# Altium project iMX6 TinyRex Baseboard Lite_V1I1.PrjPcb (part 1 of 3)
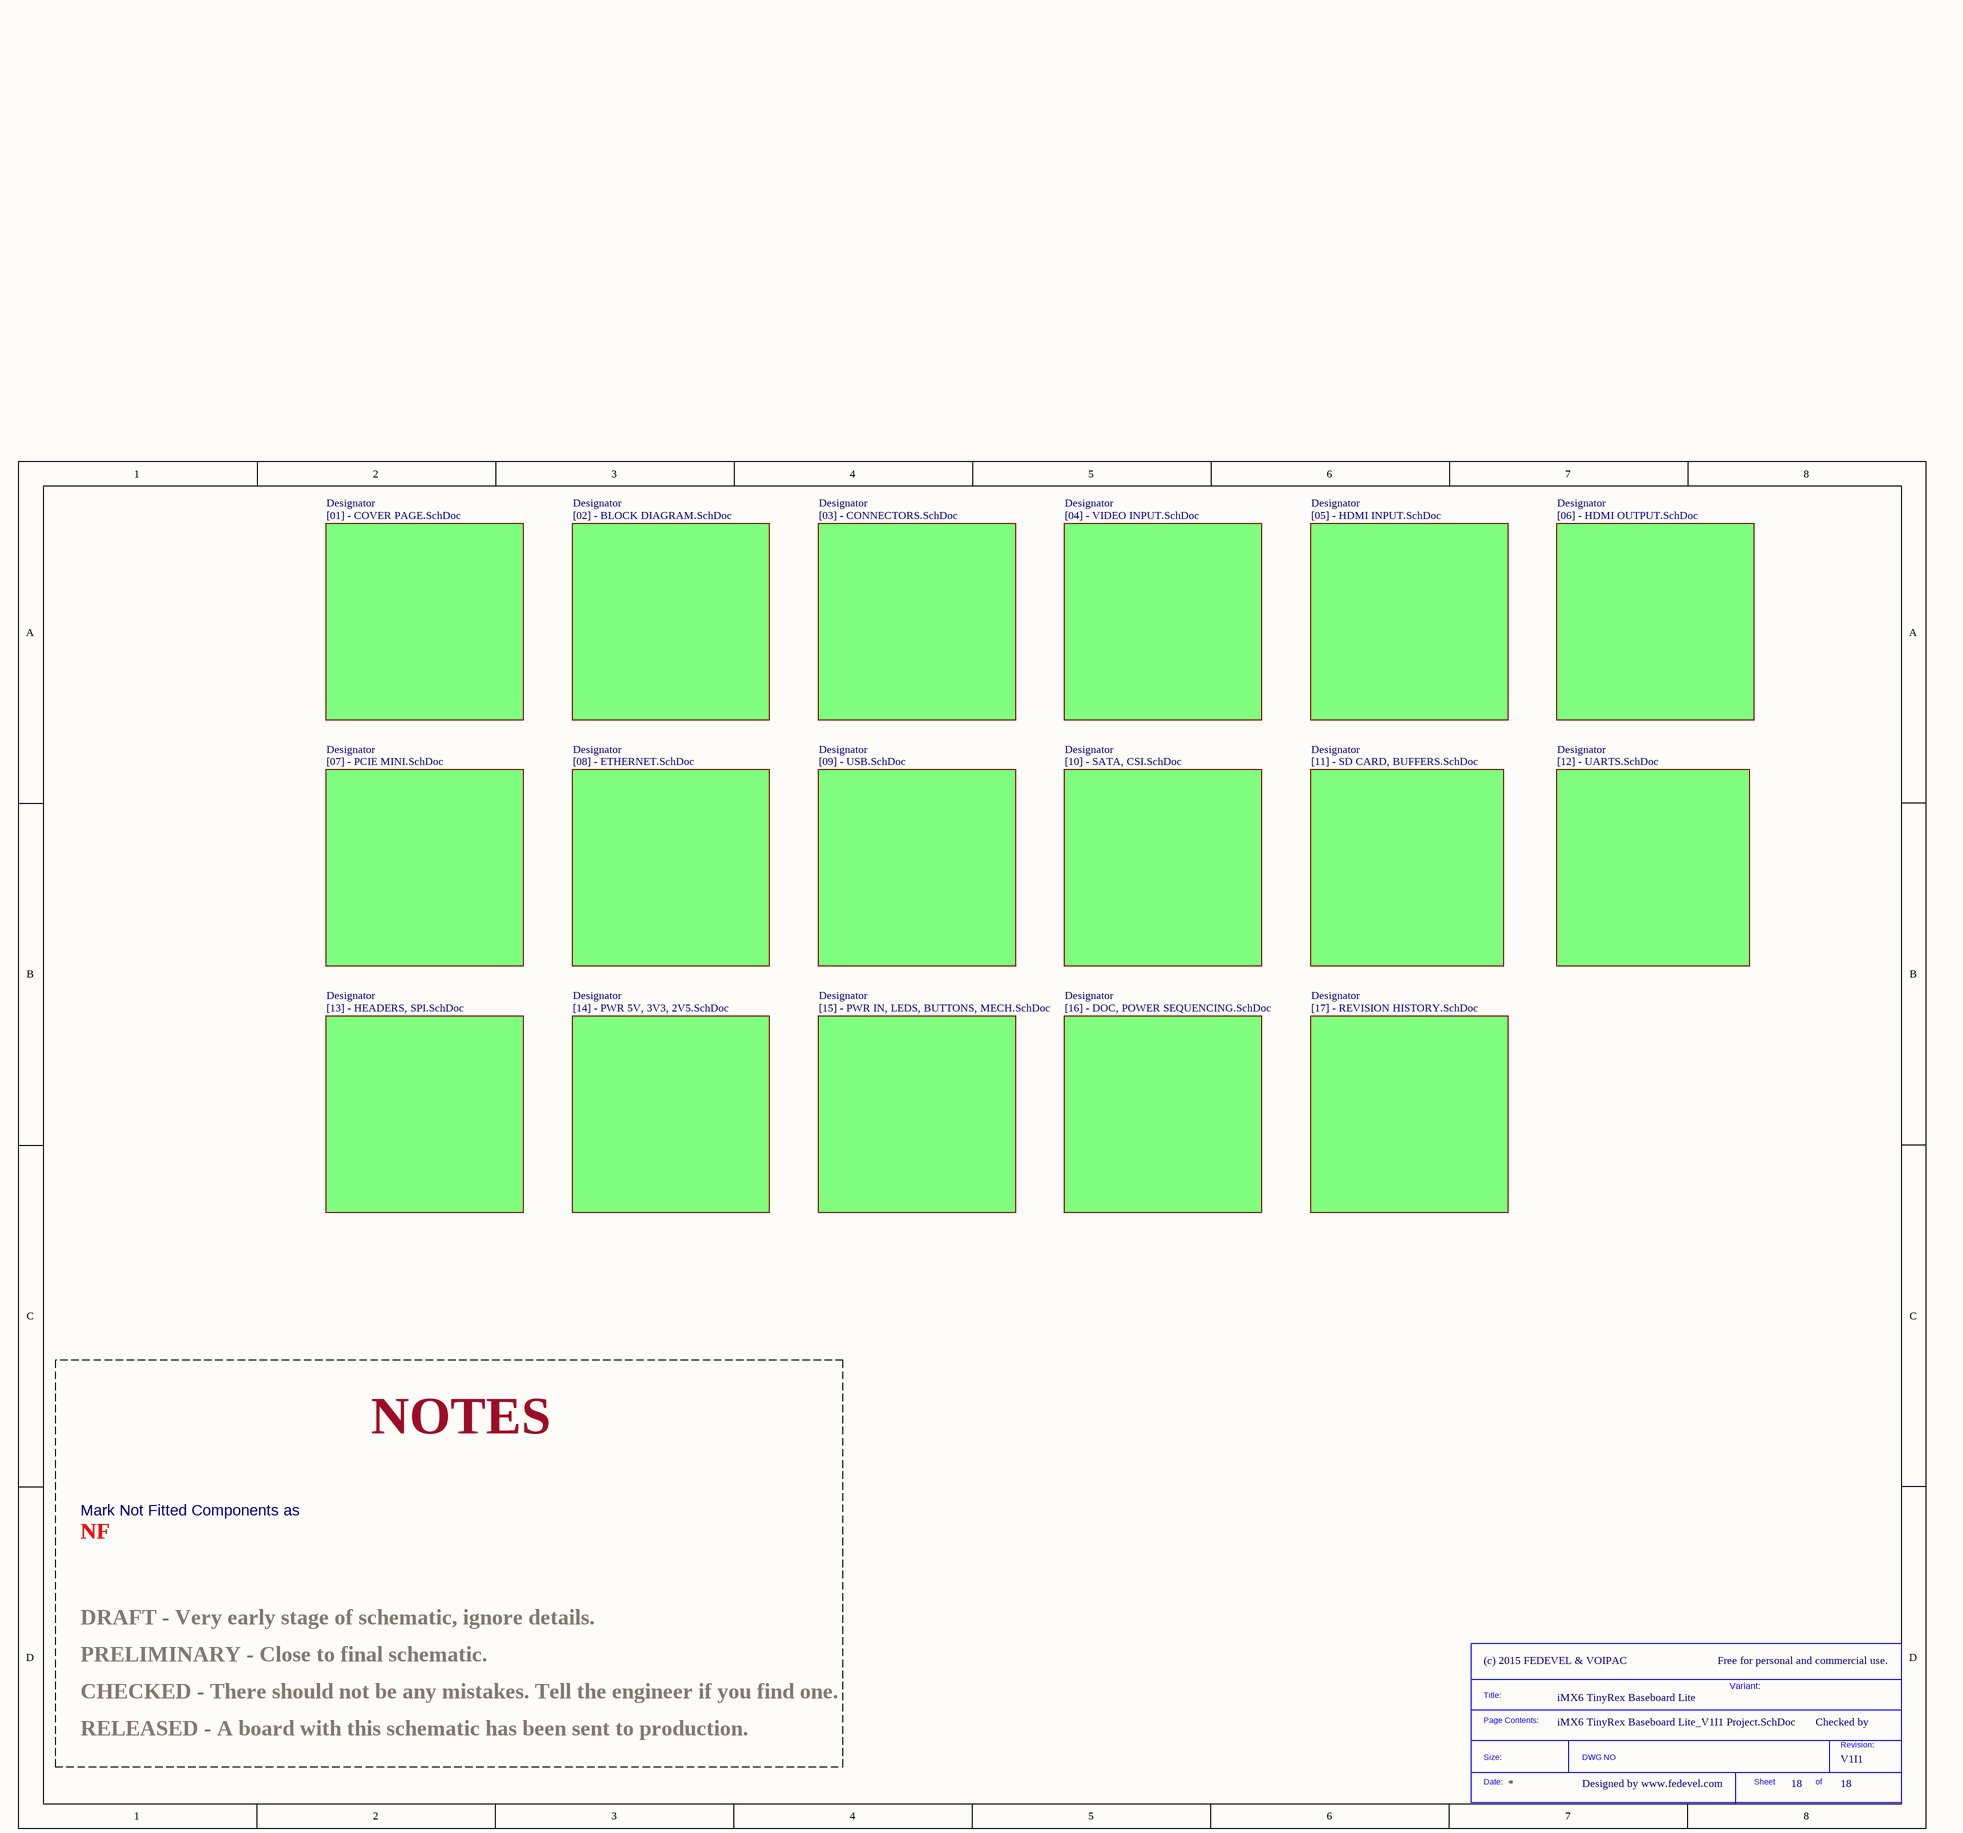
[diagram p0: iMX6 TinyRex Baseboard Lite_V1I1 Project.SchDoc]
VersionRevision: V1I1; Project: iMX6 TinyRex Baseboard Lite; NotFitted: NF; Company: (c) 2015 FEDEVEL & VOIPAC; ClientWebsite: http://www.fedevel.com/academy/; ClientContactName: Robert Feranec; ClientContactEmail: robert.feranec@fedevel.com; ClientCompanyName: FEDEVEL Academy
18 sheets, 406 parts. Net scope: flat (ports and power ports of the same name join across sheets).
Board file: iMX6 TinyRex Baseboard Lite_V1I1_PCB.PcbDoc
Sheets:
  iMX6 TinyRex Baseboard Lite_V1I1 Project.SchDoc
    Designator = [01] - COVER PAGE.SchDoc
    Designator = [02] - BLOCK DIAGRAM.SchDoc
    Designator = [15] - PWR IN, LEDS, BUTTONS, MECH.SchDoc
    Designator = [04] - VIDEO INPUT.SchDoc
    Designator = [05] - HDMI INPUT.SchDoc
    Designator = [06] - HDMI OUTPUT.SchDoc
    Designator = [07] - PCIE MINI.SchDoc
    Designator = [09] - USB.SchDoc
    Designator = [08] - ETHERNET.SchDoc
    Designator = [03] - CONNECTORS.SchDoc
    Designator = [10] - SATA, CSI.SchDoc
    Designator = [11] - SD CARD, BUFFERS.SchDoc
    Designator = [16] - DOC, POWER SEQUENCING.SchDoc
    Designator = [12] - UARTS.SchDoc
    Designator = [13] - HEADERS, SPI.SchDoc
    Designator = [14] - PWR 5V, 3V3, 2V5.SchDoc
    Designator = [17] - REVISION HISTORY.SchDoc

## Sheet iMX6 TinyRex Baseboard Lite_V1I1 Project.SchDoc
size A3; DocumentNumber: 18; SheetNumber: 18; SheetTotal: 18; PageSetup: Record=PageOptions¦CenterHorizontal=True¦CenterVertical=True¦PrintScale=1.07¦XCorrection=1.00¦YCorrection=1.00¦PrintKind=1¦BorderSize=5000000¦LeftOffset=0¦BottomOffset=0¦Orientation=2¦PaperLength=1000¦PaperWidth=1000¦Scale=100¦PaperSource=7¦PrintQuality=600¦MediaType=1¦DitherType=10¦PaperKind=A3¦PrintScaleMode=1

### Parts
(Parts that share a designator on the sheet are numbered #1, #2 ... from top to bottom, then left to right.)
*#1  SDTitleBlock  (value not drawn)  (graphical)

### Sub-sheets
Designator = [01] - COVER PAGE.SchDoc: no entries
Designator = [02] - BLOCK DIAGRAM.SchDoc: no entries
Designator = [15] - PWR IN, LEDS, BUTTONS, MECH.SchDoc: no entries
Designator = [04] - VIDEO INPUT.SchDoc: no entries
Designator = [05] - HDMI INPUT.SchDoc: no entries
Designator = [06] - HDMI OUTPUT.SchDoc: no entries
Designator = [07] - PCIE MINI.SchDoc: no entries
Designator = [09] - USB.SchDoc: no entries
Designator = [08] - ETHERNET.SchDoc: no entries
Designator = [03] - CONNECTORS.SchDoc: no entries
Designator = [10] - SATA, CSI.SchDoc: no entries
Designator = [11] - SD CARD, BUFFERS.SchDoc: no entries
Designator = [16] - DOC, POWER SEQUENCING.SchDoc: no entries
Designator = [12] - UARTS.SchDoc: no entries
Designator = [13] - HEADERS, SPI.SchDoc: no entries
Designator = [14] - PWR 5V, 3V3, 2V5.SchDoc: no entries
Designator = [17] - REVISION HISTORY.SchDoc: no entries

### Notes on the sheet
- NOTES
- NF
- Mark Not Fitted Components as
- PRELIMINARY - Close to final schematic.
- DRAFT - Very early stage of schematic, ignore details.
- Free for personal and commercial use.
- CHECKED - There should not be any mistakes. Tell the engineer if you find one.
- Variant:
- Checked by
- RELEASED - A board with this schematic has been sent to production.
- Designed by www.fedevel.com

## Sheet [01] - COVER PAGE.SchDoc
size A3; DocumentNumber: 1; SheetNumber: 1; SheetTotal: 18
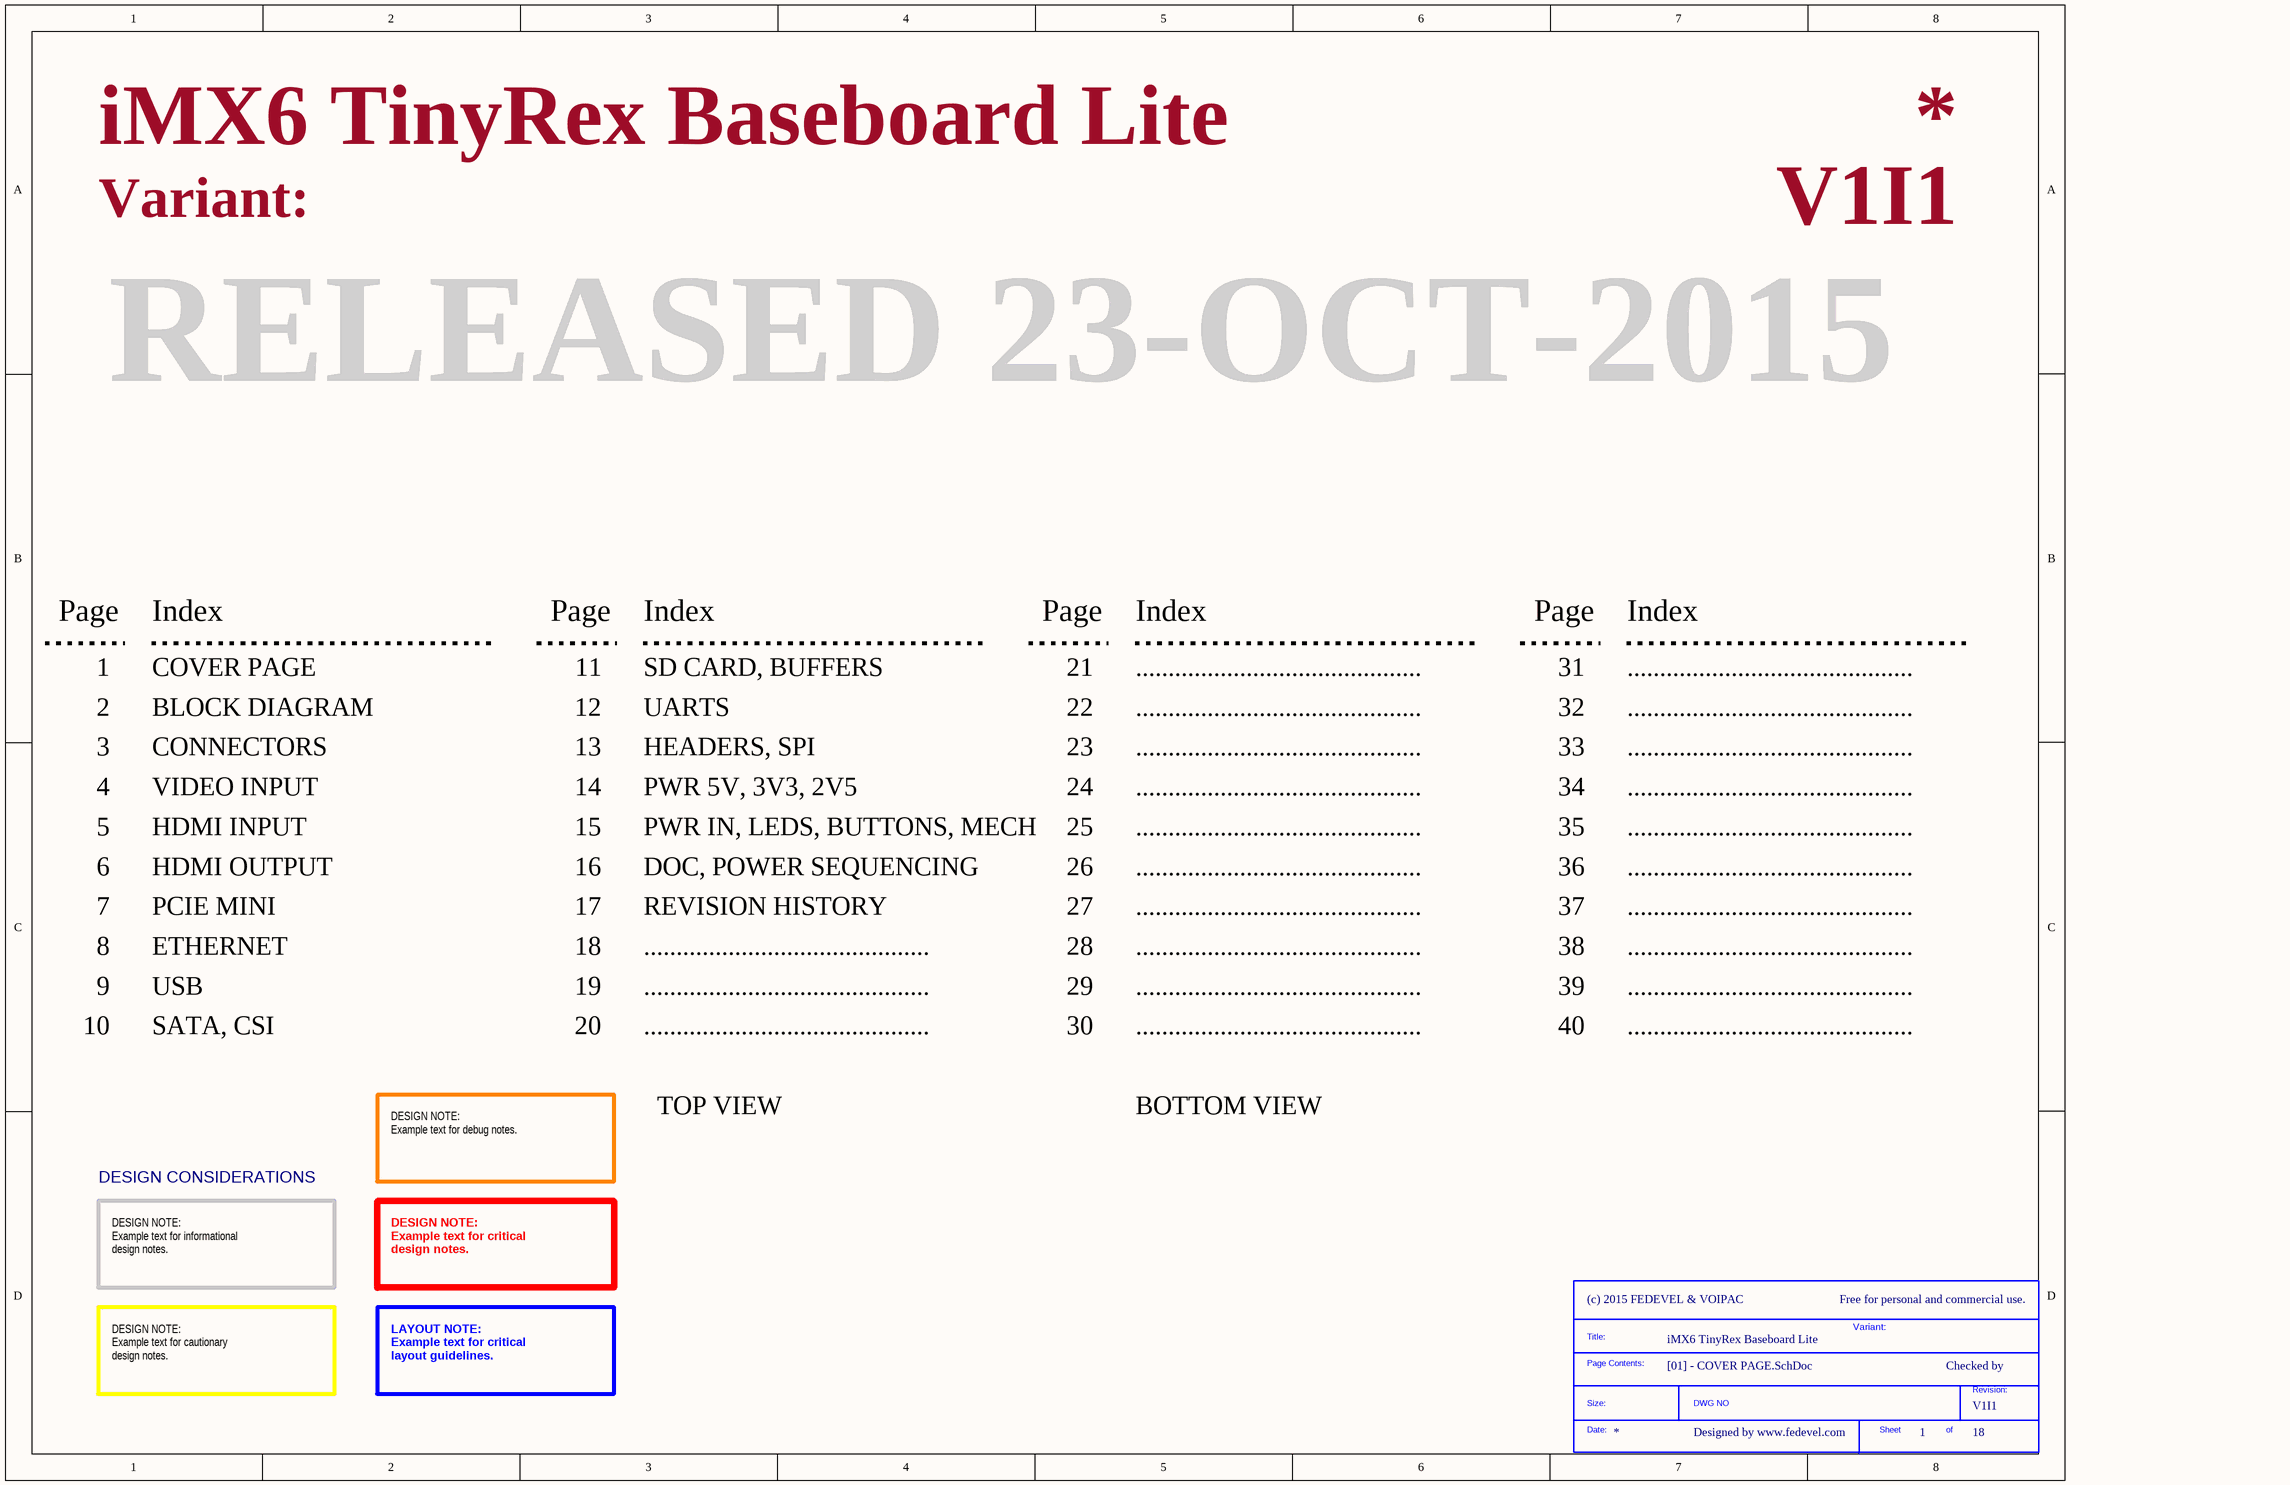
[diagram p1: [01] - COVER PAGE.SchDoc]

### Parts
(Parts that share a designator on the sheet are numbered #1, #2 ... from top to bottom, then left to right.)
*#2  SDTitleBlock  (value not drawn)  (graphical)

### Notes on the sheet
- Variant:
- RELEASED 23-OCT-2015
- Page
- Index
- 1
- COVER PAGE
- 11
- SD CARD, BUFFERS
- 21
- ............................................
- 31
- 2
- 3
- BLOCK DIAGRAM
- CONNECTORS
- 12
- 13
- UARTS
- HEADERS, SPI
- 22
- 23
- 32
- 33
- 4
- 5
- VIDEO INPUT
- HDMI INPUT
- 14
- 15
- PWR 5V, 3V3, 2V5
- PWR IN, LEDS, BUTTONS, MECH
- 24
- 25
- 34
- 35
- 6
- HDMI OUTPUT
- 16
- DOC, POWER SEQUENCING
- 26
- 36
- 7
- 8
- PCIE MINI
- ETHERNET
- 17
- 18
- REVISION HISTORY
- 27
- 28
- 37
- 38
- 9
- 10
- USB
- SATA, CSI
- 19
- 20
- 29
- 30
- 39
- 40
- DESIGN NOTE:
  Example text for debug notes.
- TOP VIEW
- BOTTOM VIEW
- DESIGN CONSIDERATIONS
- DESIGN NOTE:
  Example text for informational
  design notes.
- DESIGN NOTE:
  Example text for critical
  design notes.
- Free for personal and commercial use.
- Checked by
- DESIGN NOTE:
  Example text for cautionary
  design notes.
- LAYOUT NOTE:
  Example text for critical
  layout guidelines.
- Designed by www.fedevel.com

## Sheet [02] - BLOCK DIAGRAM.SchDoc
size A2; DocumentNumber: 2; SheetNumber: 2; SheetTotal: 18; PageSetup: Record=PageOptions¦CenterHorizontal=True¦CenterVertical=True¦PrintScale=0.73¦XCorrection=1.00¦YCorrection=1.00¦PrintKind=1¦BorderSize=5000000¦LeftOffset=0¦BottomOffset=0¦Orientation=2¦PaperLength=1000¦PaperWidth=1000¦Scale=100¦PaperSource=4¦PrintQuality=300¦MediaType=1¦DitherType=10¦PrintScaleMode=1¦PaperKind=A4¦PaperIndex=9
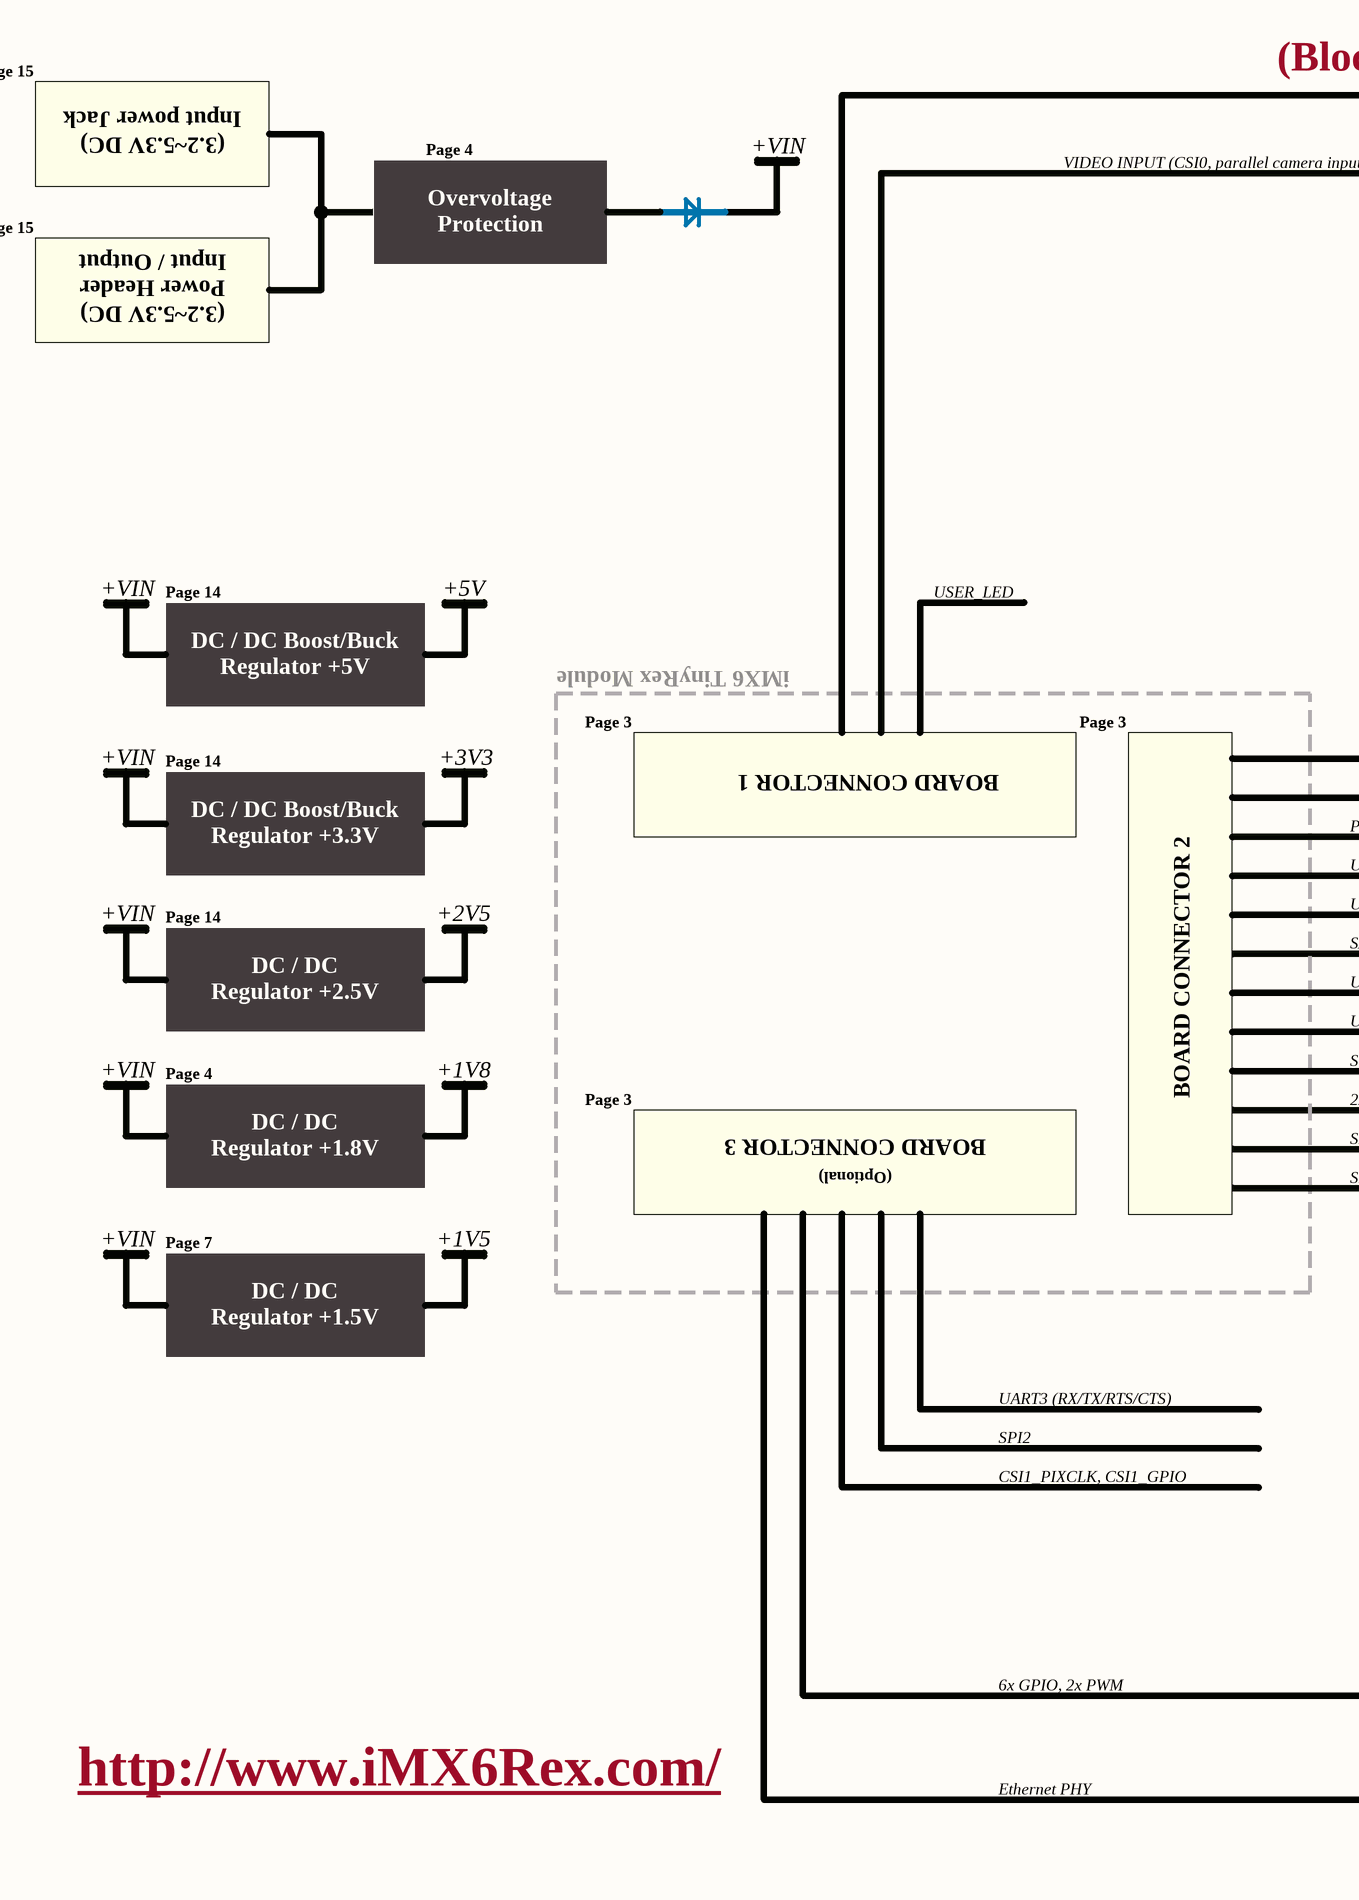
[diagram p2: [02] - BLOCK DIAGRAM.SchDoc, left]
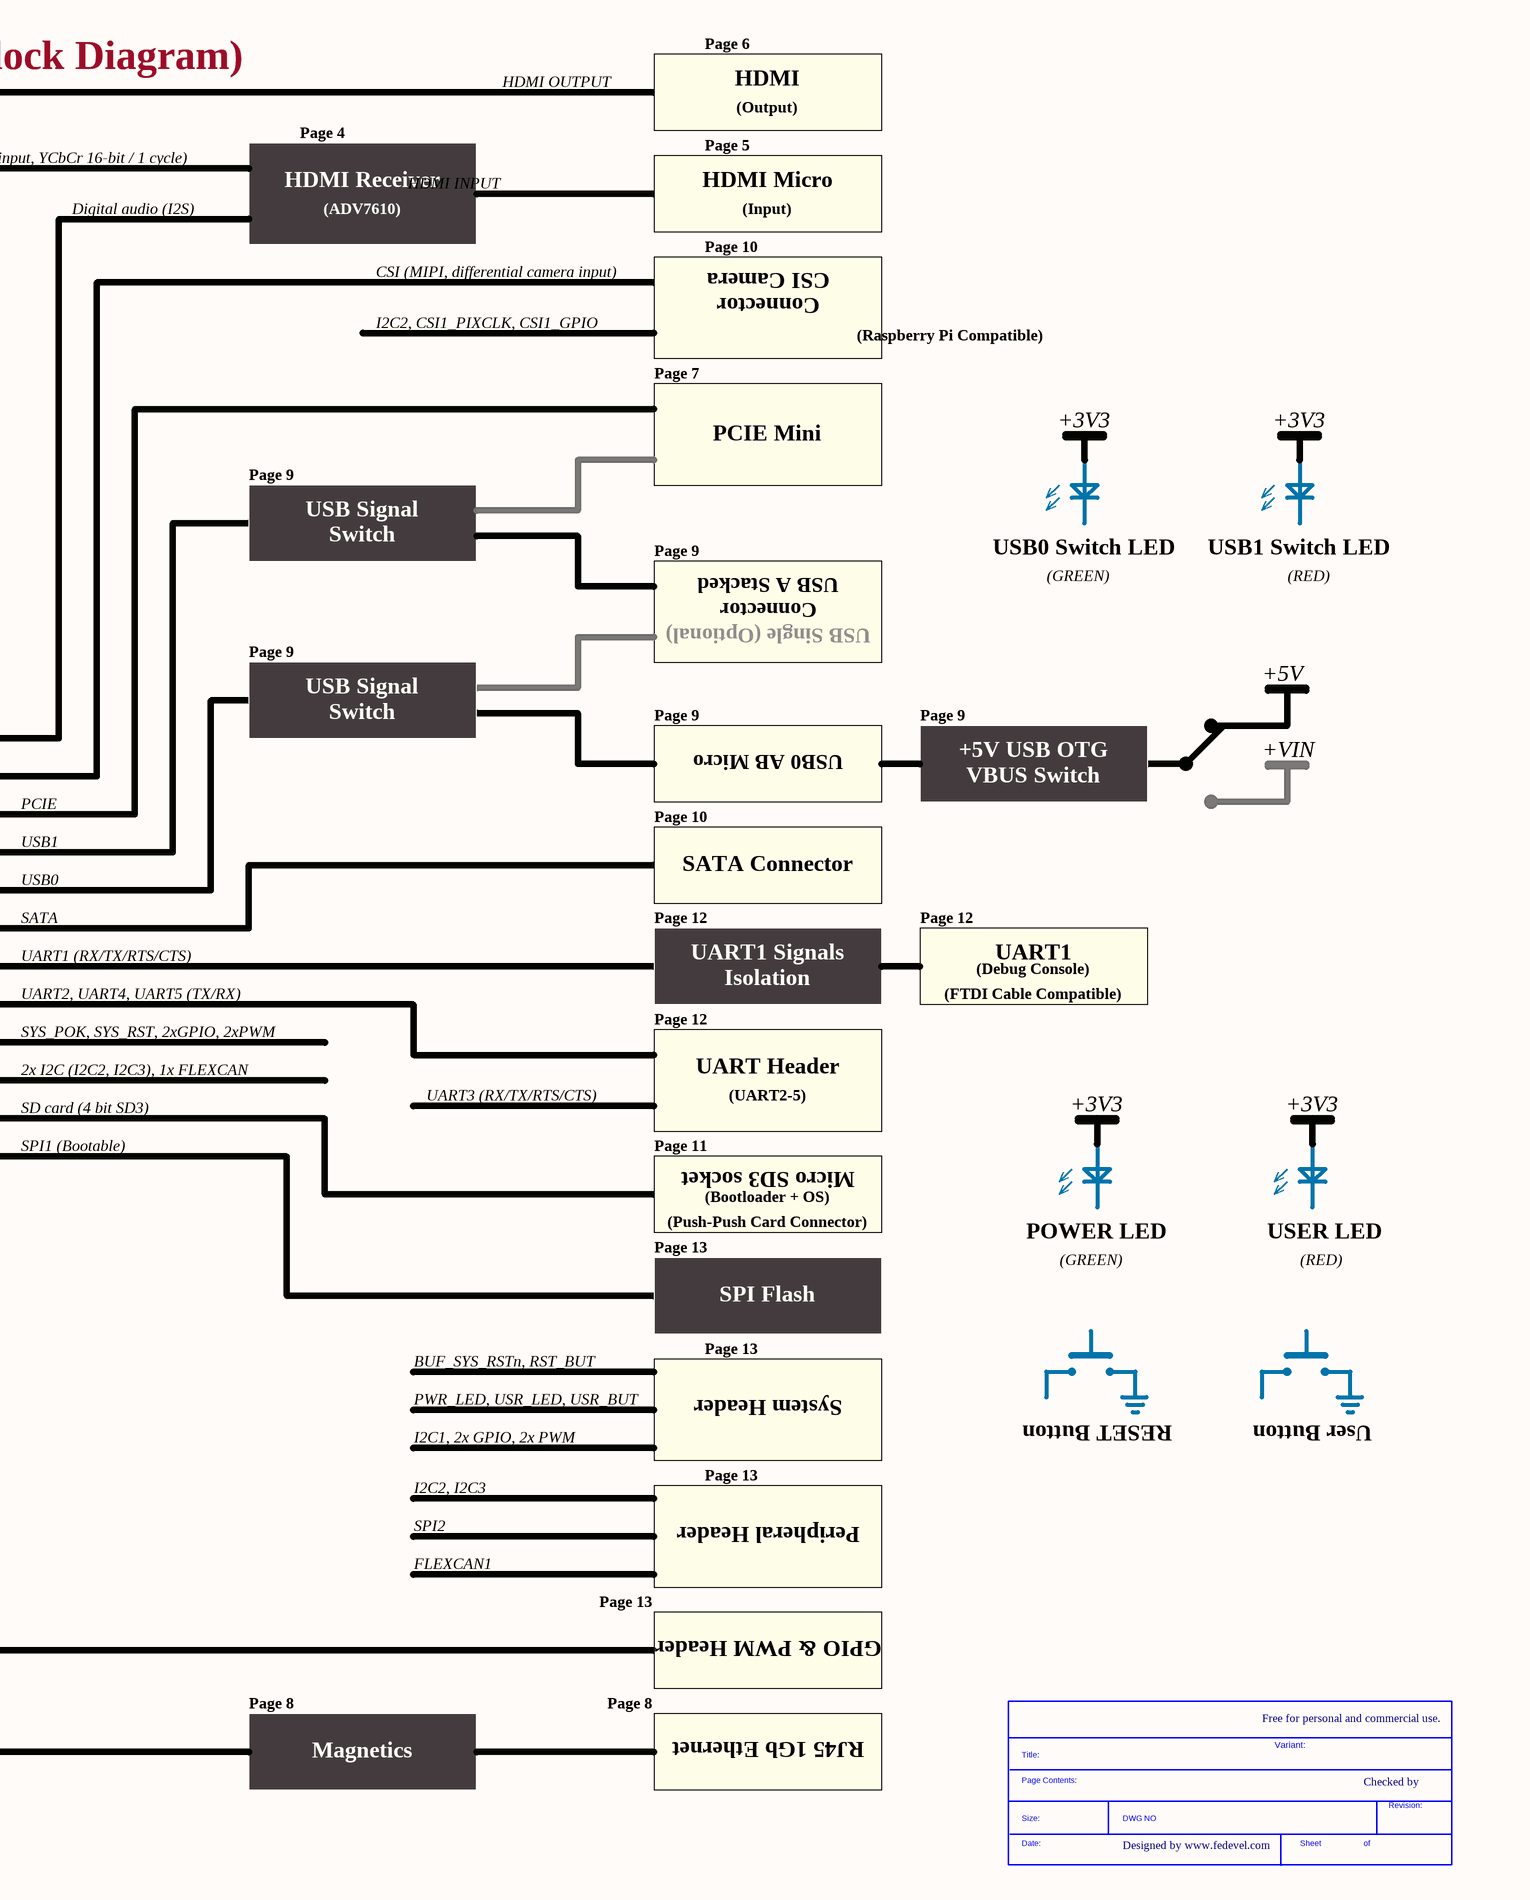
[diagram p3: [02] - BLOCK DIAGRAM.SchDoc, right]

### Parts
(Parts that share a designator on the sheet are numbered #1, #2 ... from top to bottom, then left to right.)
*#3  SDTitleBlock  (value not drawn)  (graphical)

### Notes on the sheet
- Page 15
- (Block Diagram)
- HDMI OUTPUT
- Page 6
- HDMI
- Input power Jack
- (3.2~5.3V DC)
- Page 4
- +VIN
- Page 5
- (Output)
- Overvoltage
- VIDEO INPUT (CSI0, parallel camera input, YCbCr 16-bit / 1 cycle)
- Digital audio (I2S)
- HDMI Receiver
- (ADV7610)
- HDMI INPUT
- HDMI Micro
- (Input)
- Input / Output
- Protection
- CSI (MIPI, differential camera input)
- Page 10
- Power Header
- I2C2, CSI1_PIXCLK, CSI1_GPIO
- CSI Camera
- Connector
- (Raspberry Pi Compatible)
- Page 7
- PCIE Mini
- +3V3
- Page 9
- USB Signal
- Page 14
- +5V
- USER_LED
- Switch
- USB A Stacked
- (GREEN)
- USB0 Switch LED
- (RED)
- USB1 Switch LED
- DC / DC Boost/Buck
- Regulator +5V
- USB Single (Optional)
- Page 3
- iMX6 TinyRex Module
- BOARD CONNECTOR 1
- USB0 AB Micro
- +5V USB OTG
- VBUS Switch
- Regulator +3.3V
- PCIE
- USB1
- +2V5
- USB0
- SATA Connector
- Regulator +2.5V
- DC / DC
- BOARD CONNECTOR 2
- SATA
- UART1 (RX/TX/RTS/CTS)
- Page 12
- UART1 Signals
- UART1
- (Debug Console)
- UART2, UART4, UART5 (TX/RX)
- SYS_POK, SYS_RST, 2xGPIO, 2xPWM
- Isolation
- (FTDI Cable Compatible)
- +1V8
- 2x I2C (I2C2, I2C3), 1x FLEXCAN
- UART3 (RX/TX/RTS/CTS)
- UART Header
- (UART2-5)
- Regulator +1.8V
- BOARD CONNECTOR 3
- (Optional)
- SD card (4 bit SD3)
- SPI1 (Bootable)
- Page 11
- +1V5
- Micro SD3 socket
- (Bootloader + OS)
- (Push-Push Card Connector)
- Regulator +1.5V
- Page 13
- POWER LED
- USER LED
- SPI Flash
- SPI2
- BUF_SYS_RSTn, RST_BUT
- PWR_LED, USR_LED, USR_BUT
- System Header
- CSI1_PIXCLK, CSI1_GPIO
- I2C1, 2x GPIO, 2x PWM
- RESET Button
- User Button
- I2C2, I2C3
- Peripheral Header
- FLEXCAN1
- 6x GPIO, 2x PWM
- GPIO & PWM Header
- Page 8
- Free for personal and commercial use.
- http://www.iMX6Rex.com/
- Ethernet PHY
- Magnetics
- RJ45 1Gb Ethernet
- Variant:
- Checked by
- Designed by www.fedevel.com

## Sheet [15] - PWR IN, LEDS, BUTTONS, MECH.SchDoc
size A2; DocumentNumber: 15; SheetNumber: 15; SheetTotal: 18
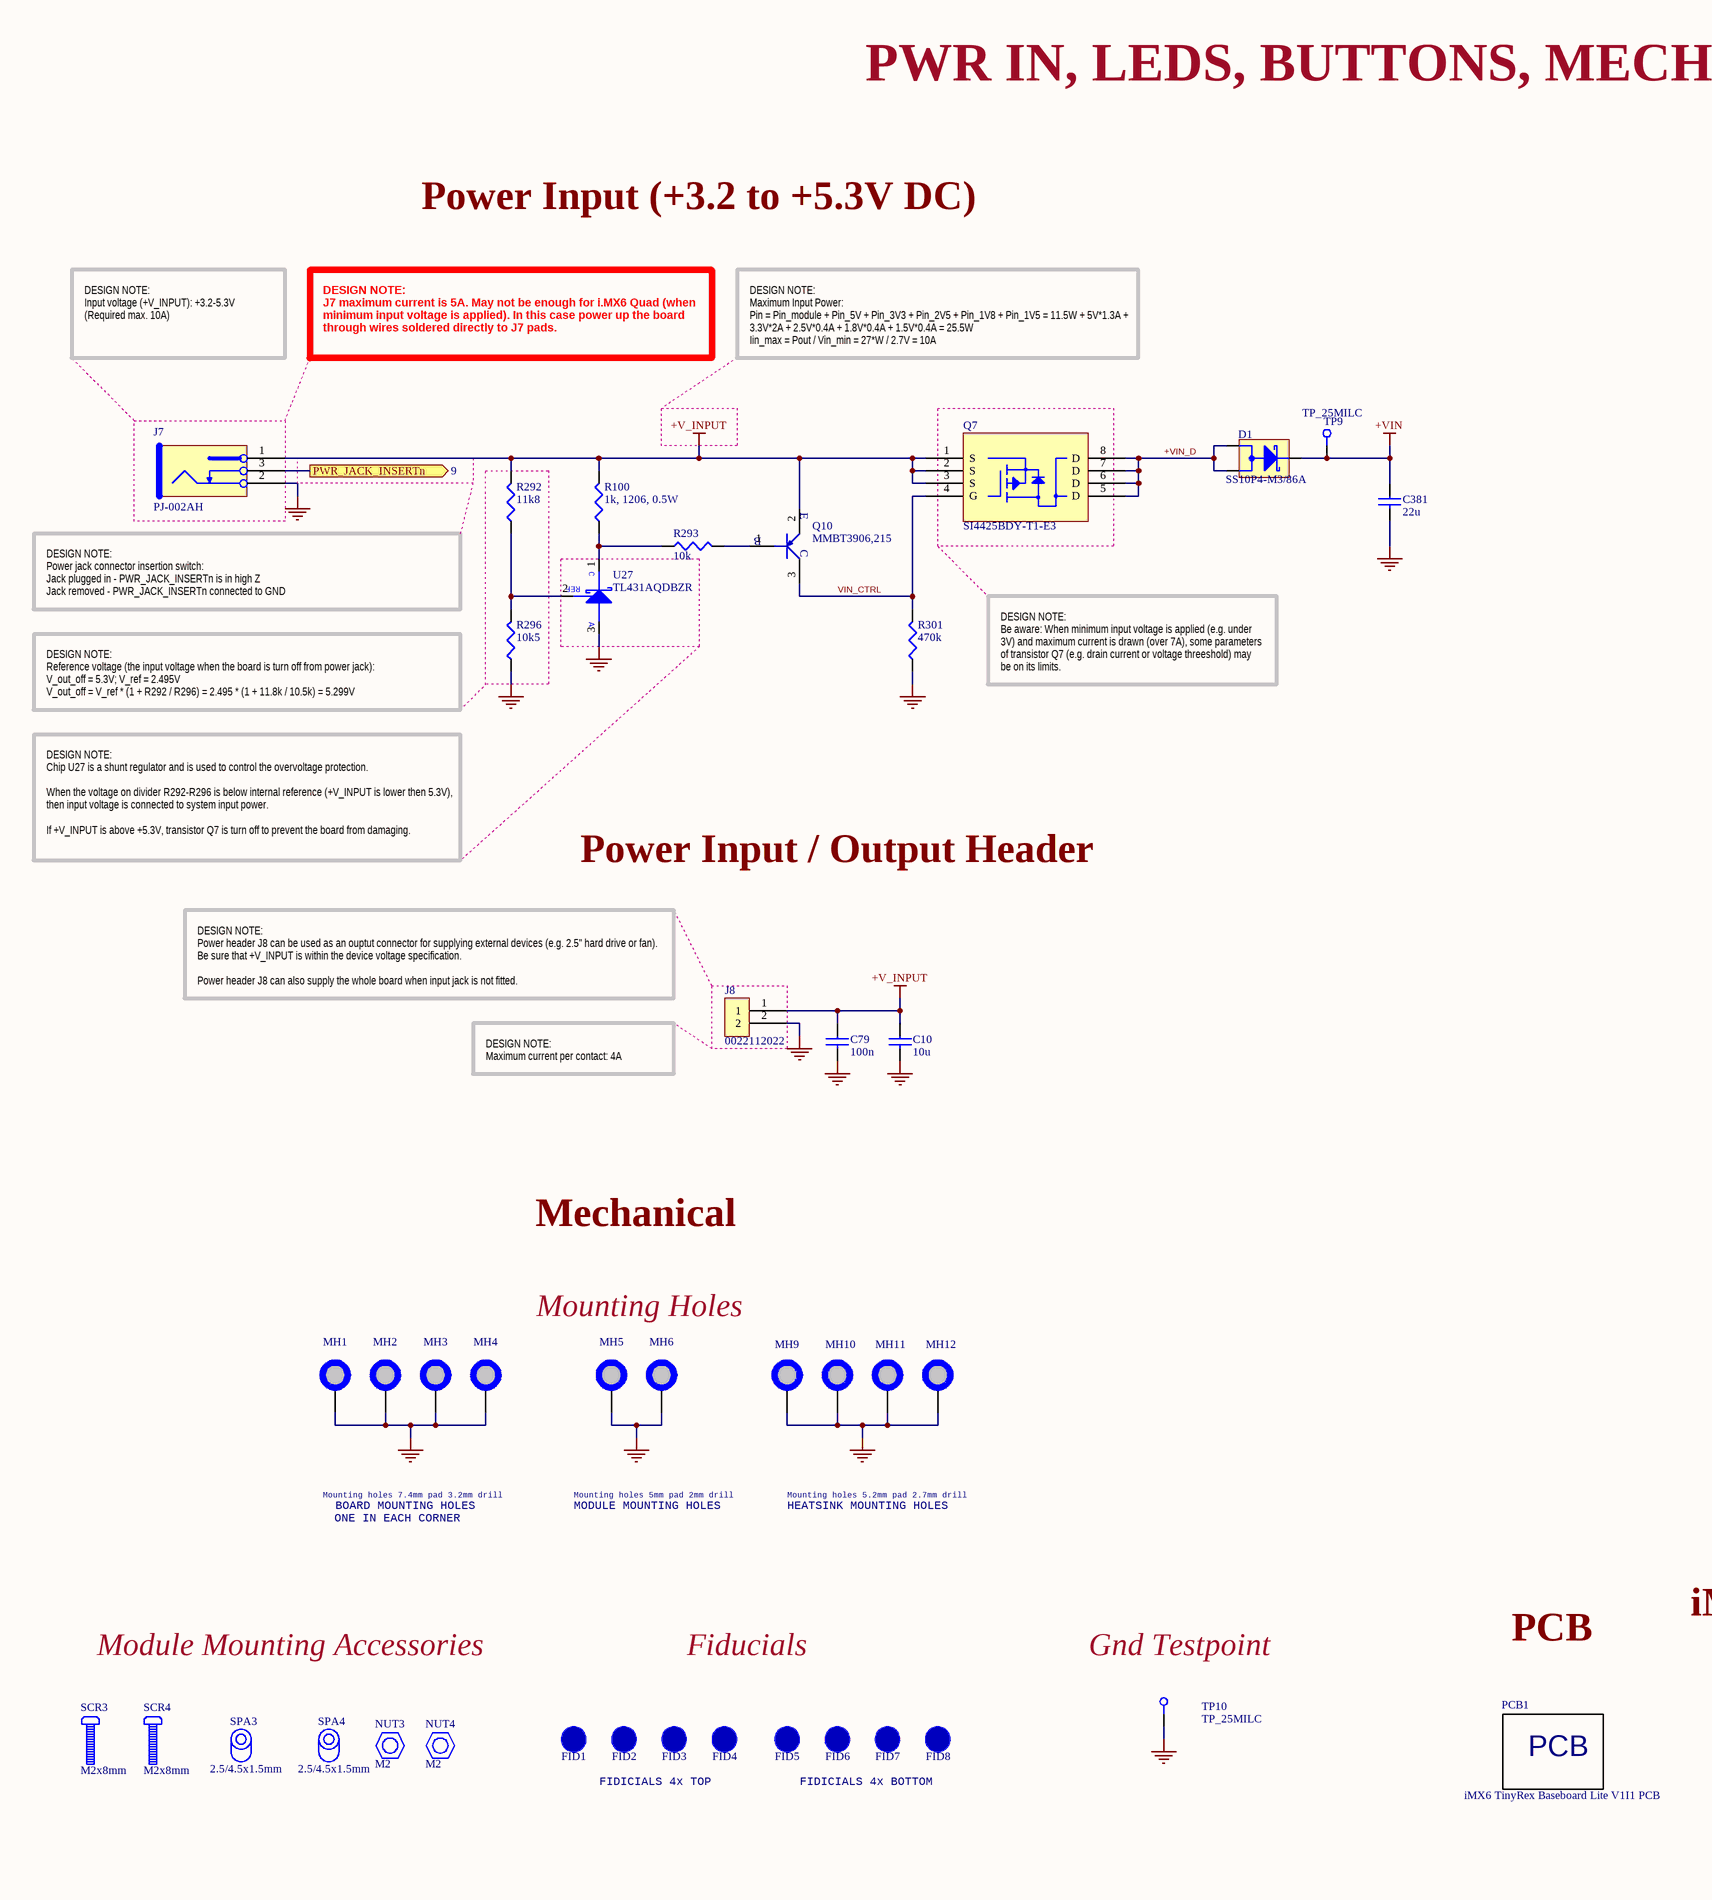
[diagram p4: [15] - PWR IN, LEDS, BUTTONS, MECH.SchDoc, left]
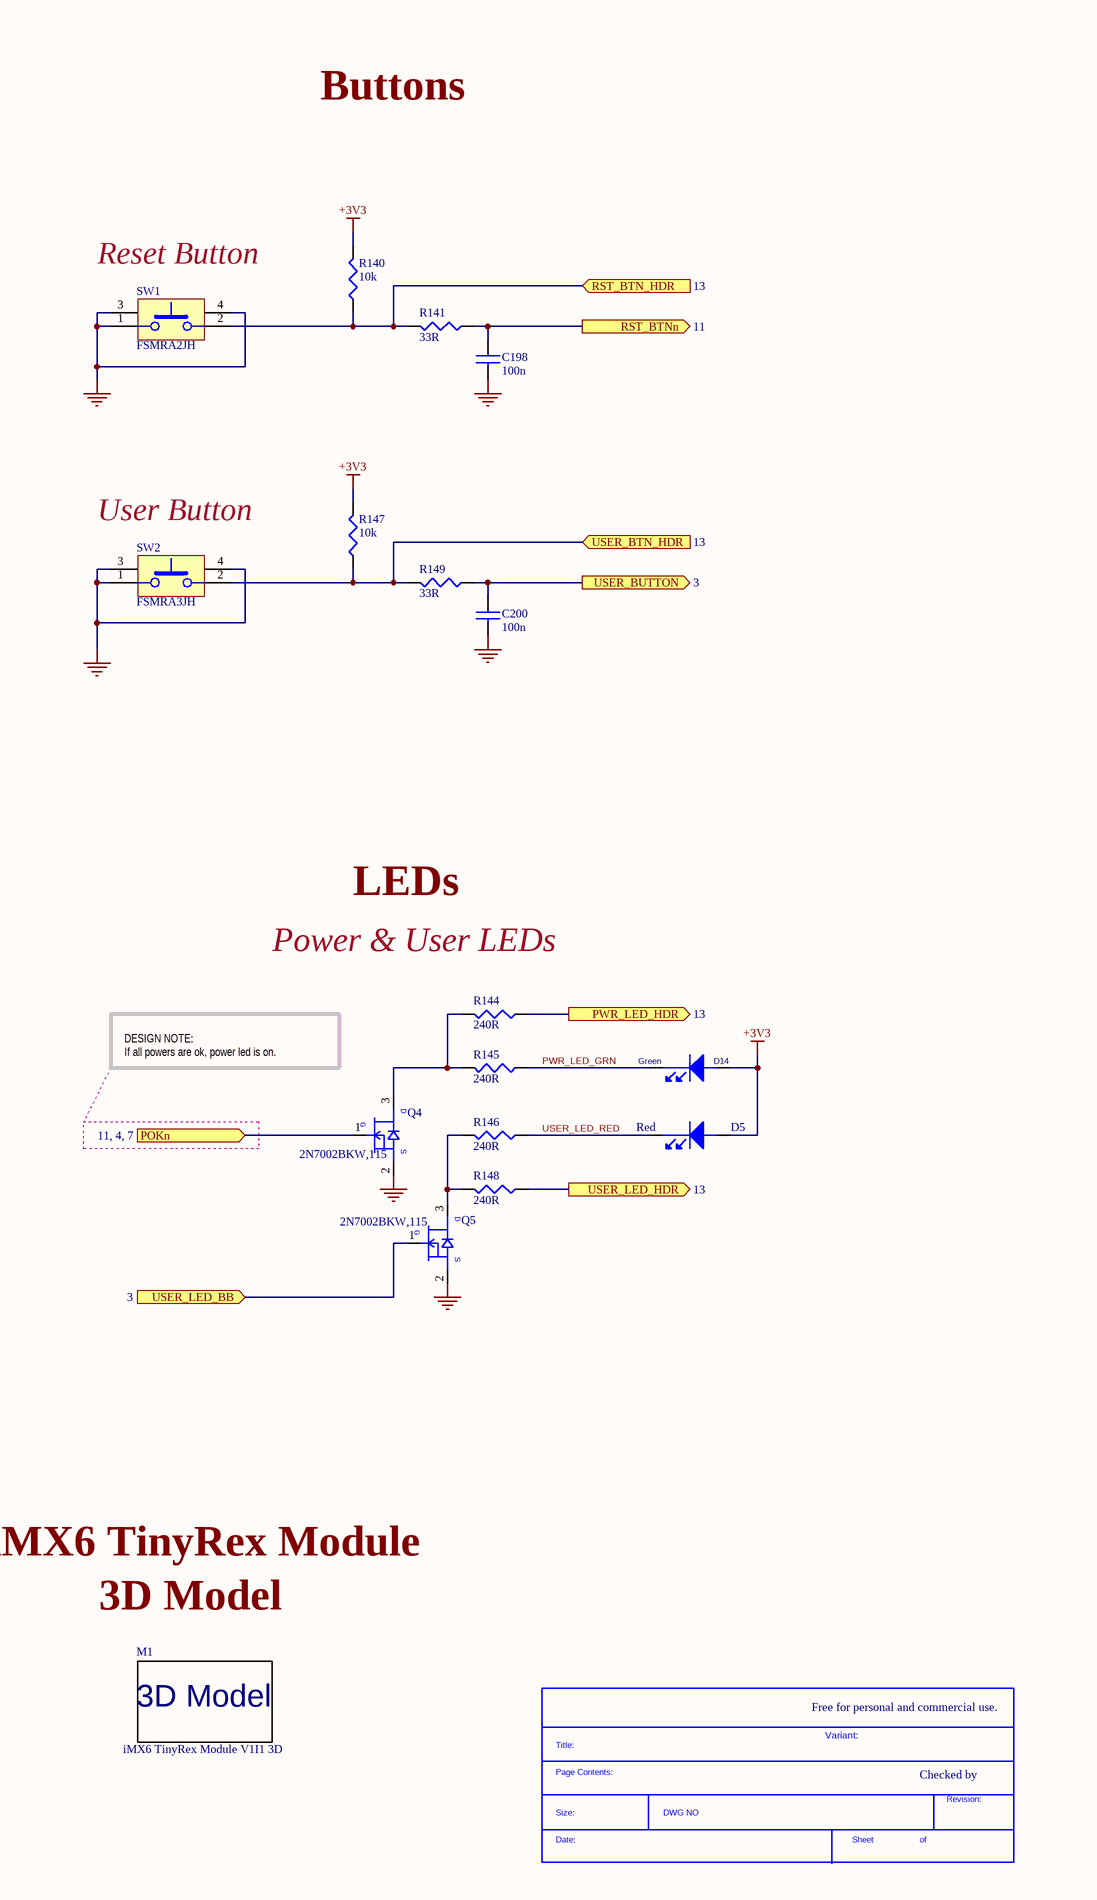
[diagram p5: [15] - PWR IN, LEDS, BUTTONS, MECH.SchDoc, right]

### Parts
(Parts that share a designator on the sheet are numbered #1, #2 ... from top to bottom, then left to right.)
*#4  SDTitleBlock  (value not drawn)  (graphical)
C10  10u  [C0603]
C79  100n  [C0402]
C198  100n  [C0402]
C200  100n  [C0402]
C381  22u  [C0603]
D1  SS10P4-M3/86A  [TO-277A (SMPC)]
D5  Red  [LED_0603]
D14  Green  [LED_0603]
FID1  FID_1MMC  [FID_40X120D]  (value not drawn)  (no BOM)
FID2  FID_1MMC  [FID_40X120D]  (value not drawn)  (no BOM)
FID3  FID_1MMC  [FID_40X120D]  (value not drawn)  (no BOM)
FID4  FID_1MMC  [FID_40X120D]  (value not drawn)  (no BOM)
FID5  FID_1MMC  [FID_40X120D]  (value not drawn)  (no BOM)
FID6  FID_1MMC  [FID_40X120D]  (value not drawn)  (no BOM)
FID7  FID_1MMC  [FID_40X120D]  (value not drawn)  (no BOM)
FID8  FID_1MMC  [FID_40X120D]  (value not drawn)  (no BOM)
J7  PJ-002AH  [POWER_JACK_5.5_2.1MM_NS_v1.1]
J8  0022112022  [HDR_1x2_2.54MM_MOLEX_KK]
M1  iMX6 TinyRex Module V1I1 3D  [iMX6 TinyRex Module 3D]  (no BOM)
MH1  MH_7.4MMC_3.2MMD  [MH_7.4MMD_3.2MMD]  (value not drawn)  (no BOM)
MH2  MH_7.4MMC_3.2MMD  [MH_7.4MMD_3.2MMD]  (value not drawn)  (no BOM)
MH3  MH_7.4MMC_3.2MMD  [MH_7.4MMD_3.2MMD]  (value not drawn)  (no BOM)
MH4  MH_7.4MMC_3.2MMD  [MH_7.4MMD_3.2MMD]  (value not drawn)  (no BOM)
MH5  MH_5MMC_2MMD  [MH_5MMD_2MMD]  (value not drawn)  (no BOM)
MH6  MH_5MMC_2MMD  [MH_5MMD_2MMD]  (value not drawn)  (no BOM)
MH9  MH_5.2MMC_2.7MMD  [MH_5.2MMD_2.7MMD]  (value not drawn)  (no BOM)
MH10  MH_5.2MMC_2.7MMD  [MH_5.2MMD_2.7MMD]  (value not drawn)  (no BOM)
MH11  MH_5.2MMC_2.7MMD  [MH_5.2MMD_2.7MMD]  (value not drawn)  (no BOM)
MH12  MH_5.2MMC_2.7MMD  [MH_5.2MMD_2.7MMD]  (value not drawn)  (no BOM)
NUT3  M2  [NUT A4 SS M2]
NUT4  M2  [NUT A4 SS M2]
PCB1  iMX6 TinyRex Baseboard Lite V1I1 PCB  (mechanical)
Q4  2N7002BKW,115  [SC70_SOT323]
Q5  2N7002BKW,115  [SC70_SOT323]
Q7  SI4425BDY-T1-E3  [8_SOIC_3.9MM]
Q10  MMBT3906,215  [SOT-23-3-123]
R100  1k, 1206, 0.5W  [R1206]
R140  10k  [R0402]
R141  33R  [R0402]
R144  240R  [R0402]
R145  240R  [R0402]
R146  240R  [R0402]
R147  10k  [R0402]
R148  240R  [R0402]
R149  33R  [R0402]
R292  11k8  [R0402]
R293  10k  [R0402]
R296  10k5  [R0402]
R301  470k  [R0402]
SCR3  M2x8mm  [SCREW M2x8]
SCR4  M2x8mm  [SCREW M2x8]
SPA3  2.5/4.5x1.5mm  [SPACER 2.5/4.5X1.5MM]
SPA4  2.5/4.5x1.5mm  [SPACER 2.5/4.5X1.5MM]
SW1  FSMRA2JH  [FSMRA2JH]
SW2  FSMRA3JH  [FSMRA3JH]
TP9  TP_25MILC  [TP_25C]  (no BOM)
TP10  TP_25MILC  [TP_25C]  (no BOM)
U27  TL431AQDBZR  [SOT-23-3-123]

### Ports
POKn (see 11, 4, 7), PWR_JACK_INSERTn (out, see 9), PWR_LED_HDR (out, see 13), RST_BTN_HDR (in, see 13), RST_BTNn (out, see 11), USER_BTN_HDR (in, see 13), USER_BUTTON (out, see 3), USER_LED_BB (in, see 3), USER_LED_HDR (out, see 13)

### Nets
+3V3: D5.2(ANODE) D14.2(ANODE) R140.2 R147.2
+V_INPUT: C10.1 C79.1 J7.1 J8.1 Q7.1(S) Q7.2(S) Q7.3(S) Q10.2(E) R100.2 R292.2
+VIN: C381.1 D1.3(CATHODE) TP9.1
GND: C10.2 C79.2 C198.2 C200.2 C381.2 J7.2 J8.2 MH1.1 MH2.1 MH3.1 MH4.1 MH5.1 MH6.1 MH9.1 MH10.1 MH11.1 MH12.1 Q4.2(SOURCE) Q5.2(SOURCE) R296.1 R301.1 SW1.1 SW1.3(MECH1) SW1.4(MECH2) SW2.1 SW2.3(MECH1) SW2.4(MECH2) TP10.1 U27.3(ANODE)
+VIN_D: D1.1(ANODE1) D1.2(ANODE2) Q7.5(D) Q7.6(D) Q7.7(D) Q7.8(D)
POKn: Q4.1(GATE) ; port POKn
PWR_JACK_INSERTn: J7.3 ; port PWR_JACK_INSERTn
PWR_LED_GRN: D14.1(cathode) R145.1
PWR_LED_HDR: R144.1 ; port PWR_LED_HDR
RST_BTN_HDR: R140.1 R141.2 SW1.2 ; port RST_BTN_HDR
RST_BTNn: C198.1 R141.1 ; port RST_BTNn
USER_BTN_HDR: R147.1 R149.2 SW2.2 ; port USER_BTN_HDR
USER_BUTTON: C200.1 R149.1 ; port USER_BUTTON
USER_LED_BB: Q5.1(GATE) ; port USER_LED_BB
USER_LED_HDR: R148.1 ; port USER_LED_HDR
USER_LED_RED: D5.1(cathode) R146.1
VIN_CTRL: Q7.4(G) Q10.3(C) R301.2
NetQ4_3: Q4.3(DRAIN) R144.2 R145.2
NetQ5_3: Q5.3(DRAIN) R146.2 R148.2
NetQ10_1: Q10.1(B) R293.2
NetR100_1: R100.1 R293.1 U27.1(cathode)
NetR292_1: R292.1 R296.2 U27.2(REF)

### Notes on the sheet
- PWR IN, LEDS, BUTTONS, MECH
- Power Input (+3.2 to +5.3V DC)
- Buttons
- DESIGN NOTE:
  Input voltage (+V_INPUT): +3.2-5.3V
  (Required max. 10A)
- DESIGN NOTE:
  J7 maximum current is 5A. May not be enough for i.MX6 Quad (when minimum input voltage is applied). In this case power up the board through wires soldered directly to J7 pads.
- DESIGN NOTE:
  Maximum Input Power:
  Pin = Pin_module + Pin_5V + Pin_3V3 + Pin_2V5 + Pin_1V8 + Pin_1V5 = 11.5W + 5V*1.3A + 3.3V*2A + 2.5V*0.4A + 1.8V*0.4A + 1.5V*0.4A = 25.5W
  Iin_max = Pout / Vin_min = 27*W / 2.7V = 10A
- (near SW1) Reset Button
- DESIGN NOTE:
  Power jack connector insertion switch:
  Jack plugged in - PWR_JACK_INSERTn is in high Z
  Jack removed - PWR_JACK_INSERTn connected to GND
- DESIGN NOTE:
  Reference voltage (the input voltage when the board is turn off from power jack):
  V_out_off = 5.3V; V_ref = 2.495V
  V_out_off = V_ref * (1 + R292 / R296) = 2.495 * (1 + 11.8k / 10.5k) = 5.299V
- DESIGN NOTE:
  Be aware: When minimum input voltage is applied (e.g. under 3V) and maximum current is drawn (over 7A), some parameters of transistor Q7 (e.g. drain current or voltage threeshold) may be on its limits.
- (near SW2) User Button
- DESIGN NOTE:
  Chip U27 is a shunt regulator and is used to control the overvoltage protection.
  When the voltage on divider R292-R296 is below internal reference (+V_INPUT is lower then 5.3V), then input voltage is connected to system input power.
  If +V_INPUT is above +5.3V, transistor Q7 is turn off to prevent the board from damaging.
- Power Input / Output Header
- DESIGN NOTE:
  Power header J8 can be used as an ouptut connector for supplying external devices (e.g. 2.5'' hard drive or fan). Be sure that +V_INPUT is within the device voltage specification.
  Power header J8 can also supply the whole board when input jack is not fitted.
- LEDs
- DESIGN NOTE:
  Maximum current per contact: 4A
- Power & User LEDs
- DESIGN NOTE:
  If all powers are ok, power led is on.
- Mechanical
- Mounting Holes
- Mounting holes 7.4mm pad 3.2mm drill
- BOARD MOUNTING HOLES
- ONE IN EACH CORNER
- MODULE MOUNTING HOLES
- Mounting holes 5mm pad 2mm drill
- HEATSINK MOUNTING HOLES
- Mounting holes 5.2mm pad 2.7mm drill
- PCB
- iMX6 TinyRex Module
- Module Mounting Accessories
- Fiducials
- Gnd Testpoint
- 3D Model
- Free for personal and commercial use.
- FIDICIALS 4x TOP
- FIDICIALS 4x BOTTOM
- Variant:
- Checked by

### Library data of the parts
C10 = C1608X5R0J106M: CAP CER 10UF 6.3V X5R 20% 0603; Manufacturer: TDK Corporation; Capacitance: 10µF; Value: 10µF; .Checked PCB: used
C79 C198 C200 = C1005X5R1H104K: CAP CER .10UF 50V X5R 10% 0402; Manufacturer: TDK Corporation; Capacitance: 0.1µF; Value: 100nF; .Checked PCB: used
C381 = C1608X5R0J226M080AC: CAP CER 22UF 6.3V 20% X5R 0603; Manufacturer: TDK Corporation; Capacitance: 22µF; .Creator: MM
D1 = SS10P4-M3/86A: DIODE SCHOTTKY 40V 10A TO277A; Manufacturer: Vishay Semiconductor Diodes Division; Voltage - Forward (Vf) (Max) @ If: 560mV @ 10A; Speed: Fast Recovery =< 500ns, > 200mA (Io); Current - Reverse Leakage @ Vr: 800µA @ 40V; Capacitance @ Vr, F: 750pF @ 4V, 1MHz; .Checked PCB: MM
D5 = LS L29K-H1J2-1-Z: LED SMARTLED RED 630NM 0603 SMD; Manufacturer: OSRAM Opto Semiconductors Inc; Millicandela Rating: 4.95mcd; Voltage - Forward (Vf) Typ: 1.8V; Current - Test: 2mA; Wavelength - Peak: 643nm; Viewing Angle: 160°; Lens Type: Diffused; Lens Style/Size: Rectangle with Flat Top, 1.3mm x 0.8mm; Luminous Flux @ Current - Test: 20 mlm; .Checked PCB: used
D14 = LG L29K-G2J1-24-Z: LED SMARTLED GREEN 570NM 0603; Manufacturer: OSRAM Opto Semiconductors Inc; .Checked PCB: used; Current - Test: 2mA; Voltage - Forward (Vf) Typ: 1.7V; Luminous Flux @ Current - Test: 12 mlm; Millicandela Rating: 3.92mcd; Wavelength - Peak: 572nm; Lens Type: Diffused; Lens Style/Size: Rectangle with Flat Top, 1.3mm x 0.8mm; Viewing Angle: 160°; Regulator Topology: Positive Fixed; Voltage - Output: 2.5V; Voltage - Input: 2.6 V ~ 6 V; Voltage - Dropout (Typical): 0.16V @ 500mA; Number of Regulators: 1; Current - Output: 500mA; Current - Limit (Min): 600mA
FID1-FID8 = FID_1MMC: Fiducial 40mil Diameter, 120mil Mask
J7 = PJ-002AH_v1.1: CONN PWR JACK 2.1X5.5MM HIGH CUR; Manufacturer: CUI Inc; .Checked PCB: MM; Mating connector: 2.1mm ID, 5.5mm OD; Gender: Male; Number of Positions/Contacts: 2 Conductors, 3 Contacts; Internal Switch(s): Single Switch, Normally Closed; Shielding: Unshielded; Voltage - Rated: 24VDC; Current Rating: 5A
J8 = 0022112022: CONN HEADER 2POS .100 VERT GOLD; Manufacturer: Molex, LLC; Connector Type: Header, Unshrouded; Number of Positions: 2; Number of Positions Loaded: All; Pitch: 0.100" (2.54mm); .Creator: MM; .Checked PCB: MM, paper model not checked
M1 = 3D_iMX6_TINYREX_MODULE_V1I1: 3D Model; .Creator: MM
MH1-MH4 = MH_7.4MMC_3.2MMD: Mounting Hole 7.4mm Diameter, 3.2mm Drill; .Creator: MM
MH5 MH6 = MH_5MMC_2MMD: Mounting Hole 5mm Diameter, 2mm Drill; .Creator: MM
MH9-MH12 = MH_5.2MMC_2.7MMD: Mounting Hole 5.2mm Diameter, 2.7mm Drill; .Creator: MM
NUT3 NUT4 = PFP1166: ROEBUCK - PFP1166 - FULL NUT A4 SS M2 (PK 100); Fastener Material: Stainless Steel; .Checked SCH: MM
PCB1 = PCB_iMX6_TinyRex_Baseboard_Lite_V1I1: .Creator: MM
Q4 Q5 = 2N7002BKW,115: MOSFET N-CH 60V 310MA SOT323; Manufacturer: NXP Semiconductors; FET Type: MOSFET N-Channel, Metal Oxide; FET Feature: Logic Level Gate; Rds On (Max) @ Id, Vgs: 1.6 Ohm @ 500mA, 10V; Vgs(th) (Max) @ Id: 2.1V @ 250µA; Gate Charge (Qg) @ Vgs: 0.6nC @ 4.5V; Input Capacitance (Ciss) @ Vds: 50pF @ 10V; Power - Max: 275mW; .Checked PCB: used
Q7 = SI4425BDY-T1-E3: MOSFET P-CH 30V 8.8A 8-SOIC; Manufacturer: Vishay Siliconix; FET Type: MOSFET P-Channel, Metal Oxide; FET Feature: Logic Level Gate; Current - Continuous Drain (Id) @ 25°C: 8.8A (Ta); Rds On (Max) @ Id, Vgs: 12 mOhm @ 11.4A, 10V; Vgs(th) (Max) @ Id: 3V @ 250µA; Gate Charge (Qg) @ Vgs: 100nC @ 10V; Power - Max: 1.5W; .Checked PCB: MM
Q10 = MMBT3906,215: TRANS PNP 40V 0.2A SOT23; Manufacturer: NXP Semiconductors; Current - Collector (Ic) (Max): 200mA; Vce Saturation (Max) @ Ib, Ic: 400mV @ 5mA, 50mA; DC Current Gain (hFE) (Min) @ Ic, Vce: 100 @ 10mA, 1V; Power - Max: 250mW; Frequency - Transition: 250MHz; .Checked PCB: MM
R100 = RNCP1206FTD1K00: RES SMD 1K OHM 1% 1/2W 1206; Manufacturer: Stackpole Electronics Inc; Power (Watts): 0.5W, 1/2W; Temperature Coefficient: ±100ppm/°C; .Checked PCB: MM
R140 R147 R293 = RC0402FR-0710KL: RES 10.0K OHM 1/16W 1% 0402 SMD; Manufacturer: Yageo; Power (Watts): 0.063W, 1/16W; .Checked PCB: used; Temperature Coefficient: ±100ppm/°C
R141 R149 = RMCF0402FT33R0: RES TF 33 OHM 1% 1/16W 0402; Manufacturer: Stackpole Electronics Inc; Resistance (Ohms): 33; Power (Watts): 0.063W, 1/16W; .Checked PCB: used; Temperature Coefficient: ±100ppm/°C
R144-R146 R148 = RMCF0402FT240R: RES TF 240 OHM 1% 0.0625W 0402; Manufacturer: Stackpole Electronics Inc; Resistance (Ohms): 240; Power (Watts): 0.063W, 1/16W; .Checked PCB: used; Temperature Coefficient: ±100ppm/°C
R292 = CRCW040211K8FKED: RES 11.8K OHM 1/16W 1% 0402 SMD; Manufacturer: Vishay Dale; Power (Watts): 0.063W, 1/16W; Temperature Coefficient: ±100ppm/°C; .Checked PCB: RF
R296 = CRCW040210K5FKED: RES 10.5K OHM 1/16W 1% 0402 SMD; Manufacturer: Vishay/Dale; Power (Watts): 0.063W, 1/16W; .Checked PCB: used; Temperature Coefficient: ±100ppm/°C
R301 = CRCW0402470KFKED: RES 470K OHM 1/16W 1% 0402 SMD; Manufacturer: Vishay Dale; Power (Watts): 0.063W, 1/16W; Temperature Coefficient: ±100ppm/°C; .Checked PCB: MM
SCR3 SCR4 = MPMS 002 0008 PH: MACHINE SCREW PAN PHILLIPS M2; Manufacturer: B&F Fastener Supply; Screw Head Type: Pan Head; Head Diameter: 0.152" (3.85mm); Head Height: 0.060" (1.52mm); Plating: Zinc; .Creator: MM
SPA3 SPA4 = SPACER 2.5/4.5X1.5MM: .Creator: MM
SW1 = FSMRA2JH: SWITCH TACTILE SPST-NO 0.05A 12V; Manufacturer: TE Connectivity; Switch Function: Off-Mom; Contact Rating @ Voltage: 0.05A @ 12VDC; Actuator Type: Standard; Actuator Height off PCB, from Pins: 3.86mm; Actuator Orientation: Side Actuated; Outline: 7.10mm x 7.00mm; Illumination: Non-Illuminated; Operating Force: 160gf; Actuator Material: Polybutylene Terephthalate (PBT); Switch Travel: 0.25mm; Mechanical Life: 100,000 Cycles; .Creator: MM; .Checked PCB: used
SW2 = FSMRA3JH: SWITCH TACTILE SPST-NO 0.05A 12V; Manufacturer: TE Connectivity; Switch Function: Off-Mom; Contact Rating @ Voltage: 0.05A @ 12VDC; Actuator Type: Standard; Actuator Height off PCB, from Pins: 5.85mm; Actuator Orientation: Side Actuated; Outline: 7.10mm x 7.00mm; Illumination: Non-Illuminated; Operating Force: 160gf; Actuator Material: Polyamide (PA), Nylon; Switch Travel: 0.25mm; Mechanical Life: 100,000 Cycles; .Creator: MM; .Checked PCB: used
TP9 TP10 = TP_25MILC: Test Point 25mil
U27 = TL431AQDBZR: IC VREF SHUNT ADJ SOT23-3; Manufacturer: Texas Instruments; Output Type: Adjustable; Voltage - Output (Min/Fixed): 2.495V; Voltage - Output (Max): 36V; Current - Output: 100mA; Tolerance: ±1%; Current - Cathode: 700µA; .Checked PCB: MM

## Sheet [04] - VIDEO INPUT.SchDoc
size A2; DocumentNumber: 4; SheetNumber: 4; SheetTotal: 18
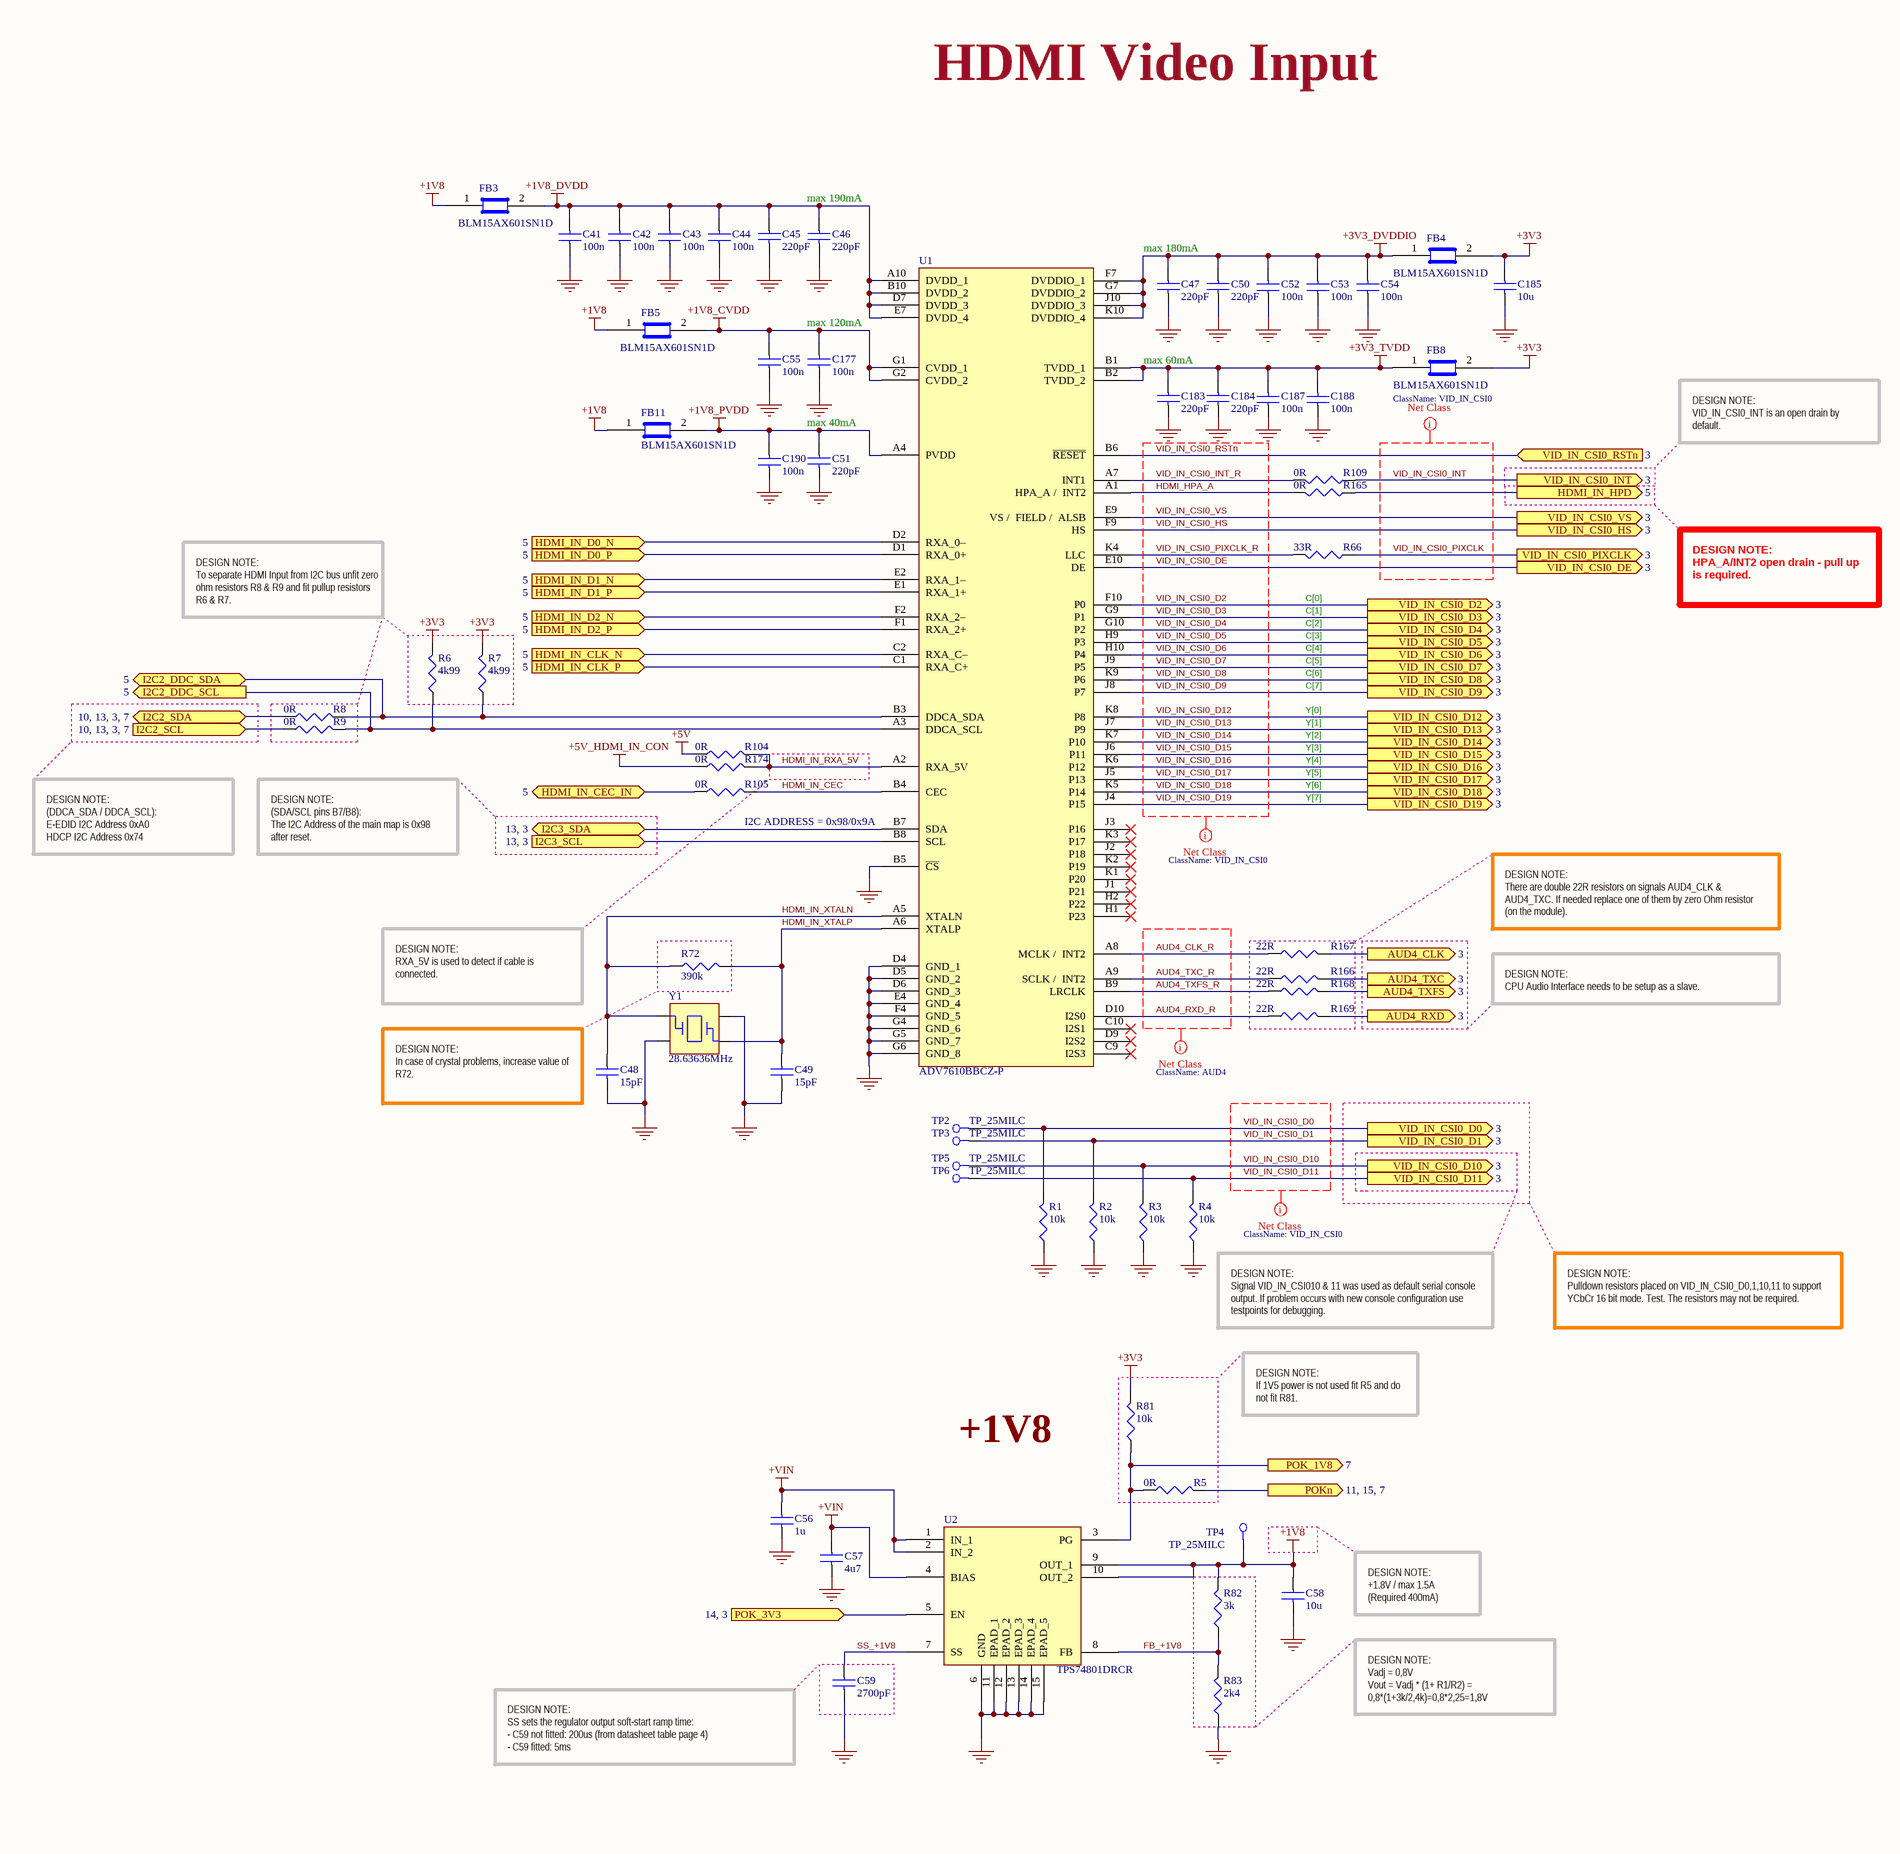
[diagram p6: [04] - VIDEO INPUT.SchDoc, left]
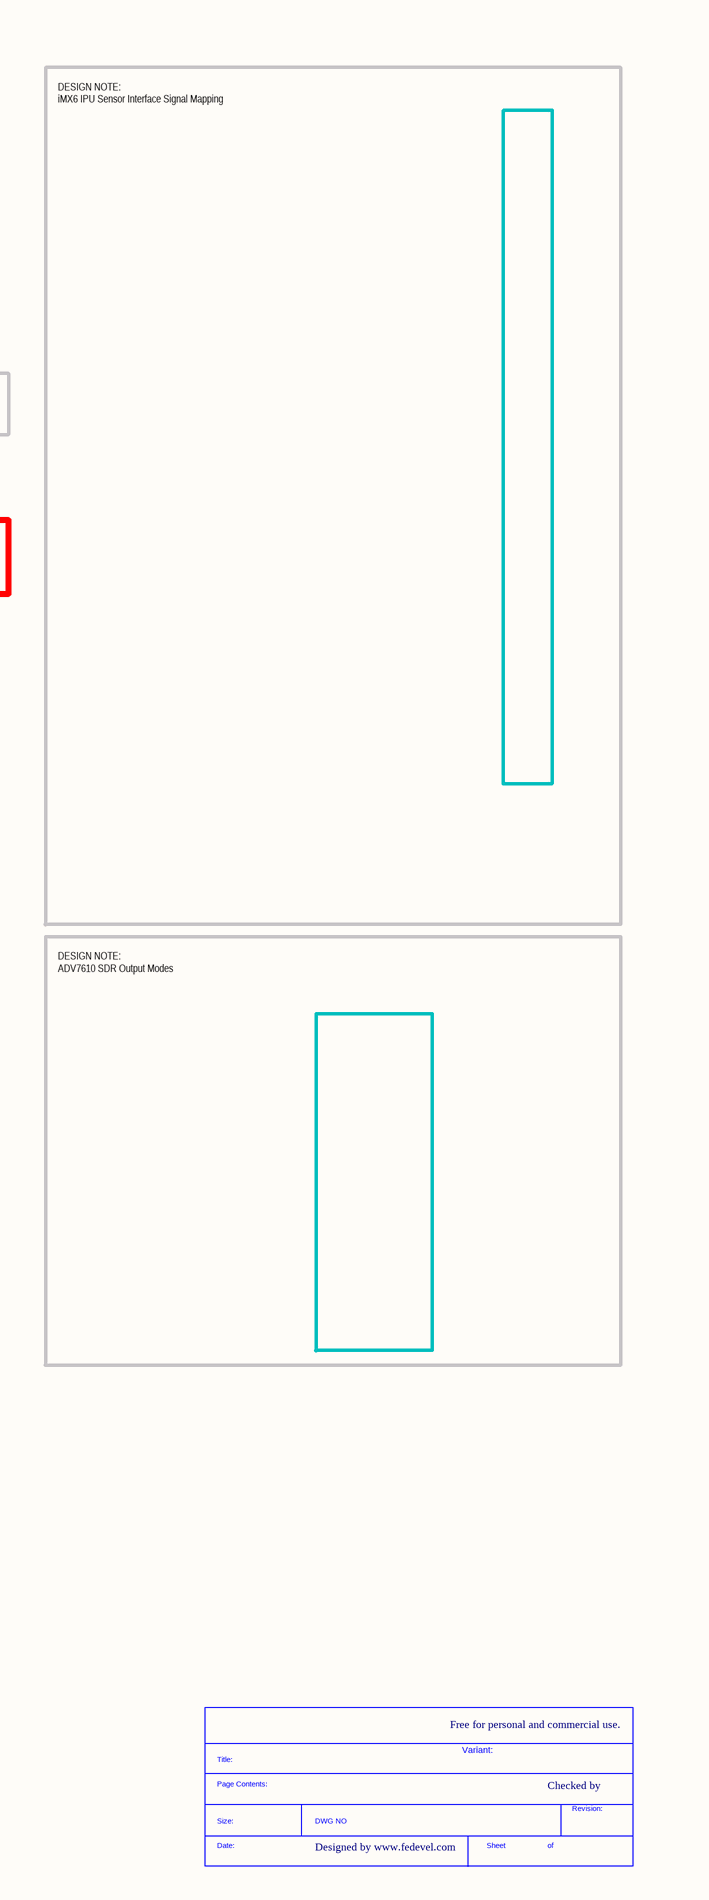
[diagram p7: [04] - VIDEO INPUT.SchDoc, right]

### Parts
(Parts that share a designator on the sheet are numbered #1, #2 ... from top to bottom, then left to right.)
*#5  SDTitleBlock  (value not drawn)  (graphical)
C41  100n  [C0402]
C42  100n  [C0402]
C43  100n  [C0402]
C44  100n  [C0402]
C45  220pF  [C0402]
C46  220pF  [C0402]
C47  220pF  [C0402]
C48  15pF  [C0402]
C49  15pF  [C0402]
C50  220pF  [C0402]
C51  220pF  [C0402]
C52  100n  [C0402]
C53  100n  [C0402]
C54  100n  [C0402]
C55  100n  [C0402]
C56  1u  [C0402]
C57  4u7  [C0402]
C58  10u  [C0603]
C59  2700pF  [C0402]
C177  100n  [C0402]
C183  220pF  [C0402]
C184  220pF  [C0402]
C185  10u  [C0603]
C187  100n  [C0402]
C188  100n  [C0402]
C190  100n  [C0402]
FB3  BLM15AX601SN1D  [C0402]
FB4  BLM15AX601SN1D  [C0402]
FB5  BLM15AX601SN1D  [C0402]
FB8  BLM15AX601SN1D  [C0402]
FB11  BLM15AX601SN1D  [C0402]
R1  10k  [R0402]
R2  10k  [R0402]
R3  10k  [R0402]
R4  10k  [R0402]
R5  0R  [R0402]
R6  4k99  [R0402]
R7  4k99  [R0402]
R8  0R  [R0402]
R9  0R  [R0402]
R66  33R  [R0402]
R72  390k  [R0402]
R81  10k  [R0402]
R82  3k  [R0402]
R83  2k4  [R0402]
R104  0R  [R0402]
R105  0R  [R0402]
R109  0R  [R0402]
R165  0R  [R0402]
R166  22R  [R0402]
R167  22R  [R0402]
R168  22R  [R0402]
R169  22R  [R0402]
R174  0R  [R0402]
TP2  TP_25MILC  [TP_25C]  (no BOM)
TP3  TP_25MILC  [TP_25C]  (no BOM)
TP4  TP_25MILC  [TP_25C]  (no BOM)
TP5  TP_25MILC  [TP_25C]  (no BOM)
TP6  TP_25MILC  [TP_25C]  (no BOM)
U1  ADV7610BBCZ-P  [76_CSP_BGA]
U2  TPS74801DRCR  [DRC (S-PVSON-N10)]
Y1  28.63636MHz  [ABM3B]

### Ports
AUD4_CLK (out, see 3), AUD4_RXD (out, see 3), AUD4_TXC (out, see 3), AUD4_TXFS (out, see 3), HDMI_IN_CEC_IN (bidir, see 5), HDMI_IN_CLK_N (in, see 5), HDMI_IN_CLK_P (in, see 5), HDMI_IN_D0_N (in, see 5), HDMI_IN_D0_P (in, see 5), HDMI_IN_D1_N (in, see 5), HDMI_IN_D1_P (in, see 5), HDMI_IN_D2_N (in, see 5), HDMI_IN_D2_P (in, see 5), HDMI_IN_HPD (out, see 5), I2C2_DDC_SCL (out, see 5), I2C2_DDC_SDA (bidir, see 5), I2C2_SCL (see 10, 13, 3, 7), I2C2_SDA (bidir, see 10, 13, 3, 7), I2C3_SCL (see 13, 3), I2C3_SDA (bidir, see 13, 3), POK_1V8 (out, see 7), POK_3V3 (see 14, 3), POKn (see 11, 15, 7), VID_IN_CSI0_D0 (out, see 3), VID_IN_CSI0_D1 (out, see 3), VID_IN_CSI0_D2 (out, see 3), VID_IN_CSI0_D3 (out, see 3), VID_IN_CSI0_D4 (out, see 3), VID_IN_CSI0_D5 (out, see 3), VID_IN_CSI0_D6 (out, see 3), VID_IN_CSI0_D7 (out, see 3), VID_IN_CSI0_D8 (out, see 3), VID_IN_CSI0_D9 (out, see 3), VID_IN_CSI0_D10 (out, see 3), VID_IN_CSI0_D11 (out, see 3), VID_IN_CSI0_D12 (out, see 3), VID_IN_CSI0_D13 (out, see 3), VID_IN_CSI0_D14 (out, see 3), VID_IN_CSI0_D15 (out, see 3), VID_IN_CSI0_D16 (out, see 3), VID_IN_CSI0_D17 (out, see 3), VID_IN_CSI0_D18 (out, see 3), VID_IN_CSI0_D19 (out, see 3), VID_IN_CSI0_DE (out, see 3), VID_IN_CSI0_HS (out, see 3), VID_IN_CSI0_INT (out, see 3), VID_IN_CSI0_PIXCLK (out, see 3), VID_IN_CSI0_RSTn (in, see 3), VID_IN_CSI0_VS (out, see 3)

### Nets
+1V8: C58.1 FB3.1 FB5.1 FB11.1 R82.2 TP4.1 U2.9(OUT_1) U2.10(OUT_2)
+1V8_CVDD: C55.2 C177.2 FB5.2 U1.G1(CVDD_1) U1.G2(CVDD_2)
+1V8_DVDD: C41.2 C42.2 C43.2 C44.2 C45.1 C46.1 FB3.2 U1.A10(DVDD_1) U1.B10(DVDD_2) U1.D7(DVDD_3) U1.E7(DVDD_4)
+1V8_PVDD: C51.1 C190.2 FB11.2 U1.A4(PVDD)
+3V3: C185.1 FB4.2 FB8.2 R6.2 R7.2 R81.2
+3V3_DVDDIO: C47.1 C50.1 C52.2 C53.2 C54.2 FB4.1 U1.F7(DVDDIO_1) U1.G7(DVDDIO_2) U1.J10(DVDDIO_3) U1.K10(DVDDIO_4)
+3V3_TVDD: C183.1 C184.1 C187.2 C188.2 FB8.1 U1.B1(TVDD_1) U1.B2(TVDD_2)
+5V: R104.1
+5V_HDMI_IN_CON: R174.1
+VIN: C56.1 C57.1 U2.1(IN_1) U2.2(IN_2) U2.4(BIAS)
GND: C41.1 C42.1 C43.1 C44.1 C45.2 C46.2 C47.2 C48.2 C49.2 C50.2 C51.2 C52.1 C53.1 C54.1 C55.1 C56.2 C57.2 C58.2 C59.2 C177.1 C183.2 C184.2 C185.2 C187.1 C188.1 C190.1 R1.1 R2.1 R3.1 R4.1 R83.1 U1.B5(~{CS}) U1.D4(GND_1) U1.D5(GND_2) U1.D6(GND_3) U1.E4(GND_4) U1.F4(GND_5) U1.G4(GND_6) U1.G5(GND_7) U1.G6(GND_8) U2.6(GND) U2.11(EPAD_1) U2.12(EPAD_2) U2.13(EPAD_3) U2.14(EPAD_4) U2.15(EPAD_5) Y1.2 Y1.4
AUD4_CLK: R167.2 ; port AUD4_CLK
AUD4_CLK_R: R167.1 U1.A8(MCLK_/__INT2)
AUD4_RXD: R169.2 ; port AUD4_RXD
AUD4_RXD_R: R169.1 U1.D10(I2S0)
AUD4_TXC: R166.2 ; port AUD4_TXC
AUD4_TXC_R: R166.1 U1.A9(SCLK_/__INT2)
AUD4_TXFS: R168.2 ; port AUD4_TXFS
AUD4_TXFS_R: R168.1 U1.B9(LRCLK)
FB_+1V8: R82.1 R83.2 U2.8(FB)
HDMI_HPA_A: R165.2 U1.A1(HPA_A_/__INT2)
HDMI_IN_CEC: R105.2 U1.B4(CEC)
HDMI_IN_CEC_IN: R105.1 ; port HDMI_IN_CEC_IN
HDMI_IN_CLK_N: U1.C2(RXA_C–) ; port HDMI_IN_CLK_N
HDMI_IN_CLK_P: U1.C1(RXA_C+) ; port HDMI_IN_CLK_P
HDMI_IN_D0_N: U1.D2(RXA_0–) ; port HDMI_IN_D0_N
HDMI_IN_D0_P: U1.D1(RXA_0+) ; port HDMI_IN_D0_P
HDMI_IN_D1_N: U1.E2(RXA_1–) ; port HDMI_IN_D1_N
HDMI_IN_D1_P: U1.E1(RXA_1+) ; port HDMI_IN_D1_P
HDMI_IN_D2_N: U1.F2(RXA_2–) ; port HDMI_IN_D2_N
HDMI_IN_D2_P: U1.F1(RXA_2+) ; port HDMI_IN_D2_P
HDMI_IN_HPD: R165.1 ; port HDMI_IN_HPD
HDMI_IN_RXA_5V: R104.2 R174.2 U1.A2(RXA_5V)
HDMI_IN_XTALN: C48.1 R72.1 U1.A5(XTALN) Y1.1
HDMI_IN_XTALP: C49.1 R72.2 U1.A6(XTALP) Y1.3
I2C2_DDC_SCL: R6.1 R9.2 U1.A3(DDCA_SCL) ; port I2C2_DDC_SCL
I2C2_DDC_SDA: R7.1 R8.2 U1.B3(DDCA_SDA) ; port I2C2_DDC_SDA
I2C2_SCL: R9.1 ; port I2C2_SCL
I2C2_SDA: R8.1 ; port I2C2_SDA
I2C3_SCL: U1.B8(SCL) ; port I2C3_SCL
I2C3_SDA: U1.B7(SDA) ; port I2C3_SDA
POK_1V8: R5.1 R81.1 U2.3(PG) ; port POK_1V8
POK_3V3: U2.5(EN) ; port POK_3V3
POKn: R5.2 ; port POKn
SS_+1V8: C59.1 U2.7(SS)
VID_IN_CSI0_D0: R1.2 TP2.1 ; port VID_IN_CSI0_D0
VID_IN_CSI0_D1: R2.2 TP3.1 ; port VID_IN_CSI0_D1
VID_IN_CSI0_D2: U1.F10(P0) ; port VID_IN_CSI0_D2
VID_IN_CSI0_D3: U1.G9(P1) ; port VID_IN_CSI0_D3
VID_IN_CSI0_D4: U1.G10(P2) ; port VID_IN_CSI0_D4
VID_IN_CSI0_D5: U1.H9(P3) ; port VID_IN_CSI0_D5
VID_IN_CSI0_D6: U1.H10(P4) ; port VID_IN_CSI0_D6
VID_IN_CSI0_D7: U1.J9(P5) ; port VID_IN_CSI0_D7
VID_IN_CSI0_D8: U1.K9(P6) ; port VID_IN_CSI0_D8
VID_IN_CSI0_D9: U1.J8(P7) ; port VID_IN_CSI0_D9
VID_IN_CSI0_D10: R3.2 TP5.1 ; port VID_IN_CSI0_D10
VID_IN_CSI0_D11: R4.2 TP6.1 ; port VID_IN_CSI0_D11
VID_IN_CSI0_D12: U1.K8(P8) ; port VID_IN_CSI0_D12
VID_IN_CSI0_D13: U1.J7(P9) ; port VID_IN_CSI0_D13
VID_IN_CSI0_D14: U1.K7(P10) ; port VID_IN_CSI0_D14
VID_IN_CSI0_D15: U1.J6(P11) ; port VID_IN_CSI0_D15
VID_IN_CSI0_D16: U1.K6(P12) ; port VID_IN_CSI0_D16
VID_IN_CSI0_D17: U1.J5(P13) ; port VID_IN_CSI0_D17
VID_IN_CSI0_D18: U1.K5(P14) ; port VID_IN_CSI0_D18
VID_IN_CSI0_D19: U1.J4(P15) ; port VID_IN_CSI0_D19
VID_IN_CSI0_DE: U1.E10(DE) ; port VID_IN_CSI0_DE
VID_IN_CSI0_HS: U1.F9(HS) ; port VID_IN_CSI0_HS
VID_IN_CSI0_INT: R109.1 ; port VID_IN_CSI0_INT
VID_IN_CSI0_INT_R: R109.2 U1.A7(INT1)
VID_IN_CSI0_PIXCLK: R66.1 ; port VID_IN_CSI0_PIXCLK
VID_IN_CSI0_PIXCLK_R: R66.2 U1.K4(LLC)
VID_IN_CSI0_RSTn: U1.B6(~{RESET}) ; port VID_IN_CSI0_RSTn
VID_IN_CSI0_VS: U1.E9(VS_/__FIELD_/__ALSB) ; port VID_IN_CSI0_VS

Not connected (* = marked no-connect by the designer): U1 C9(I2S3)* C10(I2S1)* D9(I2S2)* H1(P23)* H2(P22)* J1(P21)* J2(P18)* J3(P16)* K1(P20)* K2(P19)* K3(P17)*

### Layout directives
net class VID_IN_CSI0: HDMI_HPA_A, VID_IN_CSI0_D0, VID_IN_CSI0_D1, VID_IN_CSI0_D2, VID_IN_CSI0_D3, VID_IN_CSI0_D4, VID_IN_CSI0_D5, VID_IN_CSI0_D6, VID_IN_CSI0_D7, VID_IN_CSI0_D8, VID_IN_CSI0_D9, VID_IN_CSI0_D10, VID_IN_CSI0_D11, VID_IN_CSI0_D12, VID_IN_CSI0_D13, VID_IN_CSI0_D14, VID_IN_CSI0_D15, VID_IN_CSI0_D16, VID_IN_CSI0_D17, VID_IN_CSI0_D18, VID_IN_CSI0_D19, VID_IN_CSI0_DE, VID_IN_CSI0_HS, VID_IN_CSI0_INT, VID_IN_CSI0_INT_R, VID_IN_CSI0_PIXCLK, VID_IN_CSI0_PIXCLK_R, VID_IN_CSI0_RSTn, VID_IN_CSI0_VS
net class AUD4: AUD4_CLK_R, AUD4_RXD_R, AUD4_TXC_R, AUD4_TXFS_R

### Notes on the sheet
- HDMI Video Input
- DESIGN NOTE:
  iMX6 IPU Sensor Interface Signal Mapping
- (near C46) max 190mA
- max 180mA
- (near C177) max 120mA
- max 60mA
- (near C51) max 40mA
- DESIGN NOTE:
  VID_IN_CSI0_INT is an open drain by default.
- DESIGN NOTE:
  HPA_A/INT2 open drain - pull up is required.
- DESIGN NOTE:
  To separate HDMI Input from I2C bus unfit zero ohm resistors R8 & R9 and fit pullup resistors R6 & R7.
- (near R66) C[0]
- C[1]
- C[2]
- C[3]
- C[4]
- C[5]
- C[6]
- C[7]
- Y[0]
- Y[1]
- Y[2]
- Y[3]
- Y[4]
- Y[5]
- (near R105) I2C ADDRESS = 0x98/0x9A
- Y[6]
- Y[7]
- DESIGN NOTE:
  (DDCA_SDA / DDCA_SCL):
  E-EDID I2C Address 0xA0
  HDCP I2C Address 0x74
- DESIGN NOTE:
  (SDA/SCL pins B7/B8):
  The I2C Address of the main map is 0x98 after reset.
- DESIGN NOTE:
  There are double 22R resistors on signals AUD4_CLK & AUD4_TXC. If needed replace one of them by zero Ohm resistor (on the module).
- DESIGN NOTE:
  RXA_5V is used to detect if cable is connected.
- DESIGN NOTE:
  CPU Audio Interface needs to be setup as a slave.
- DESIGN NOTE:
  ADV7610 SDR Output Modes
- (near C48) DESIGN NOTE:
  In case of crystal problems, increase value of R72.
- (near R4) DESIGN NOTE:
  Signal VID_IN_CSI010 & 11 was used as default serial console output. If problem occurs with new console configuration use testpoints for debugging.
- DESIGN NOTE:
  Pulldown resistors placed on VID_IN_CSI0_D0,1,10,11 to support YCbCr 16 bit mode. Test. The resistors may not be required.
- +1V8
- DESIGN NOTE:
  If 1V5 power is not used fit R5 and do not fit R81.
- DESIGN NOTE:
  +1.8V / max 1.5A
  (Required 400mA)
- DESIGN NOTE:
  Vadj = 0,8V
  Vout = Vadj * (1+ R1/R2) = 0,8*(1+3k/2,4k)=0,8*2,25=1,8V
- DESIGN NOTE:
  SS sets the regulator output soft-start ramp time:
  - C59 not fitted: 200us (from datasheet table page 4)
  - C59 fitted: 5ms
- Free for personal and commercial use.
- Variant:
- Checked by
- Designed by www.fedevel.com

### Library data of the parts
C41-C44 C52-C55 C177 C187 C188 C190 = C1005X5R1H104K: as C79 on sheet [15] - PWR IN, LEDS, BUTTONS, MECH
C45-C47 C50 C51 C183 C184 = C1005X7R1H221K: CAP CER 220PF 50V X7R 10% 0402; Manufacturer: TDK Corporation; .Checked PCB: used
C48 C49 = C1005C0G1H150J: CAP CER 15PF 50V 5% NP0 0402; Manufacturer: TDK Corporation; Temperature Coefficient: C0G, NP0; .Checked PCB: used
C56 = C1005X5R1C105K: CAP CER 1.0UF 16V X5R 0402; Manufacturer: TDK Corporation; Capacitance: 1.0µF; Value: 1uF; .Checked PCB: used; Tolerance: ±10%
C57 = C1005X5R1A475M: CAP CER 4.7UF 10V 20% X5R 0402; Manufacturer: TDK Corporation; Capacitance: 4.7µF; .Checked PCB: used
C58 C185 = C1608X5R0J106M: as C10 on sheet [15] - PWR IN, LEDS, BUTTONS, MECH
C59 = GRM155R71H272KA01D: CAP CER 2700PF 50V 10% X7R 0402; Manufacturer: Murata Electronics North America; .Checked PCB: used
FB3-FB5 FB8 FB11 = BLM15AX601SN1D: FERRITE CHIP 600 OHM 0402 420mA; Manufacturer: Murata Electronics North America; .Checked PCB: used; Impedance @ Frequency: 600 Ohm @ 100MHz; DC Resistance (DCR): 340 mOhm Max; Filter Type: Differential Mode - Single; Number of Lines: 1
R1-R4 R81 = RC0402FR-0710KL: as R140 on sheet [15] - PWR IN, LEDS, BUTTONS, MECH
R5 R8 R9 R104 R105 R109 R165 R174 = RC0402JR-070RL: RES 0.0 OHM 1/16W 0402 SMD; Manufacturer: Yageo; Resistance (Ohms): 0.0; Power (Watts): 0.063W, 1/16W; Tolerance: Jumper; .Checked PCB: used
R6 R7 = RMCF0402FT4K99: RES TF 4.99K OHM 1% 1/16W 0402; Manufacturer: Stackpole Electronics Inc; Power (Watts): 0.063W, 1/16W; .Checked PCB: used; Temperature Coefficient: ±100ppm/°C
R66 = RMCF0402FT33R0: as R141 on sheet [15] - PWR IN, LEDS, BUTTONS, MECH
R72 = CRCW0402390KFKED: RES 390K OHM 1/16W 1% 0402 SMD; Manufacturer: Vishay Dale; Power (Watts): 0.063W, 1/16W; Temperature Coefficient: ±100ppm/°C; .Creator: MM; .Checked SCH: used
R82 = RC0402FR-073KL: RES 3K OHM 1/16W 1% 0402 SMD; Manufacturer: Yageo; Power (Watts): 0.063W, 1/16W; Temperature Coefficient: ±100ppm/°C; .Creator: MM; .Checked SCH: used
R83 = CRCW04022K40FKED: RES 2.40K OHM 1/16W 1% 0402 SMD; Manufacturer: Vishay Dale; Resistance (Ohms): 2.4K; Power (Watts): 0.063W, 1/16W; Temperature Coefficient: ±100ppm/°C; .Checked PCB: used
R166-R169 = RC0402FR-0722RL: RES 22.0 OHM 1/16W 1% 0402 SMD; Manufacturer: Yageo; Resistance (Ohms): 22; Power (Watts): 0.063W, 1/16W; .Checked PCB: used; Temperature Coefficient: ±100ppm/°C
TP2-TP6 = TP_25MILC: Test Point 25mil
U1 = ADV7610BBCZ-P: IC RCVR HDMI 165MHZ LP 76-CSBGA; Manufacturer: Analog Devices Inc; .Creator: MM; .Checked PCB: used
U2 = TPS74801DRCR: IC REG LDO ADJ 1.5A 10SON; Manufacturer: Texas Instruments; Number of Regulators: 1; Regulator Topology: Positive Adjustable; Voltage - Input: 0.8 V ~ 5.5 V; Voltage - Output: 0.8 V ~ 3.6 V; Voltage - Dropout (Typical): 0.06V @ 1.5A; Current - Output: 1.5A (Max); Current - Limit (Min): 2A; .Creator: MM; .Checked PCB: used
Y1 = ABM3B-28.63636MHZ-10-1-U-T: CRYSTAL 28.63636MHZ 10PF SMD; Manufacturer: Abracon Corporation; Frequency Stability: ±10ppm; ESR (Equivalent Series Resistance): 50 Ohm; Operating Mode: Fundamental; .Creator: MM; .Checked PCB: MM, paper model not checked

## Sheet [05] - HDMI INPUT.SchDoc
size A3; DocumentNumber: 5; SheetNumber: 5; SheetTotal: 18
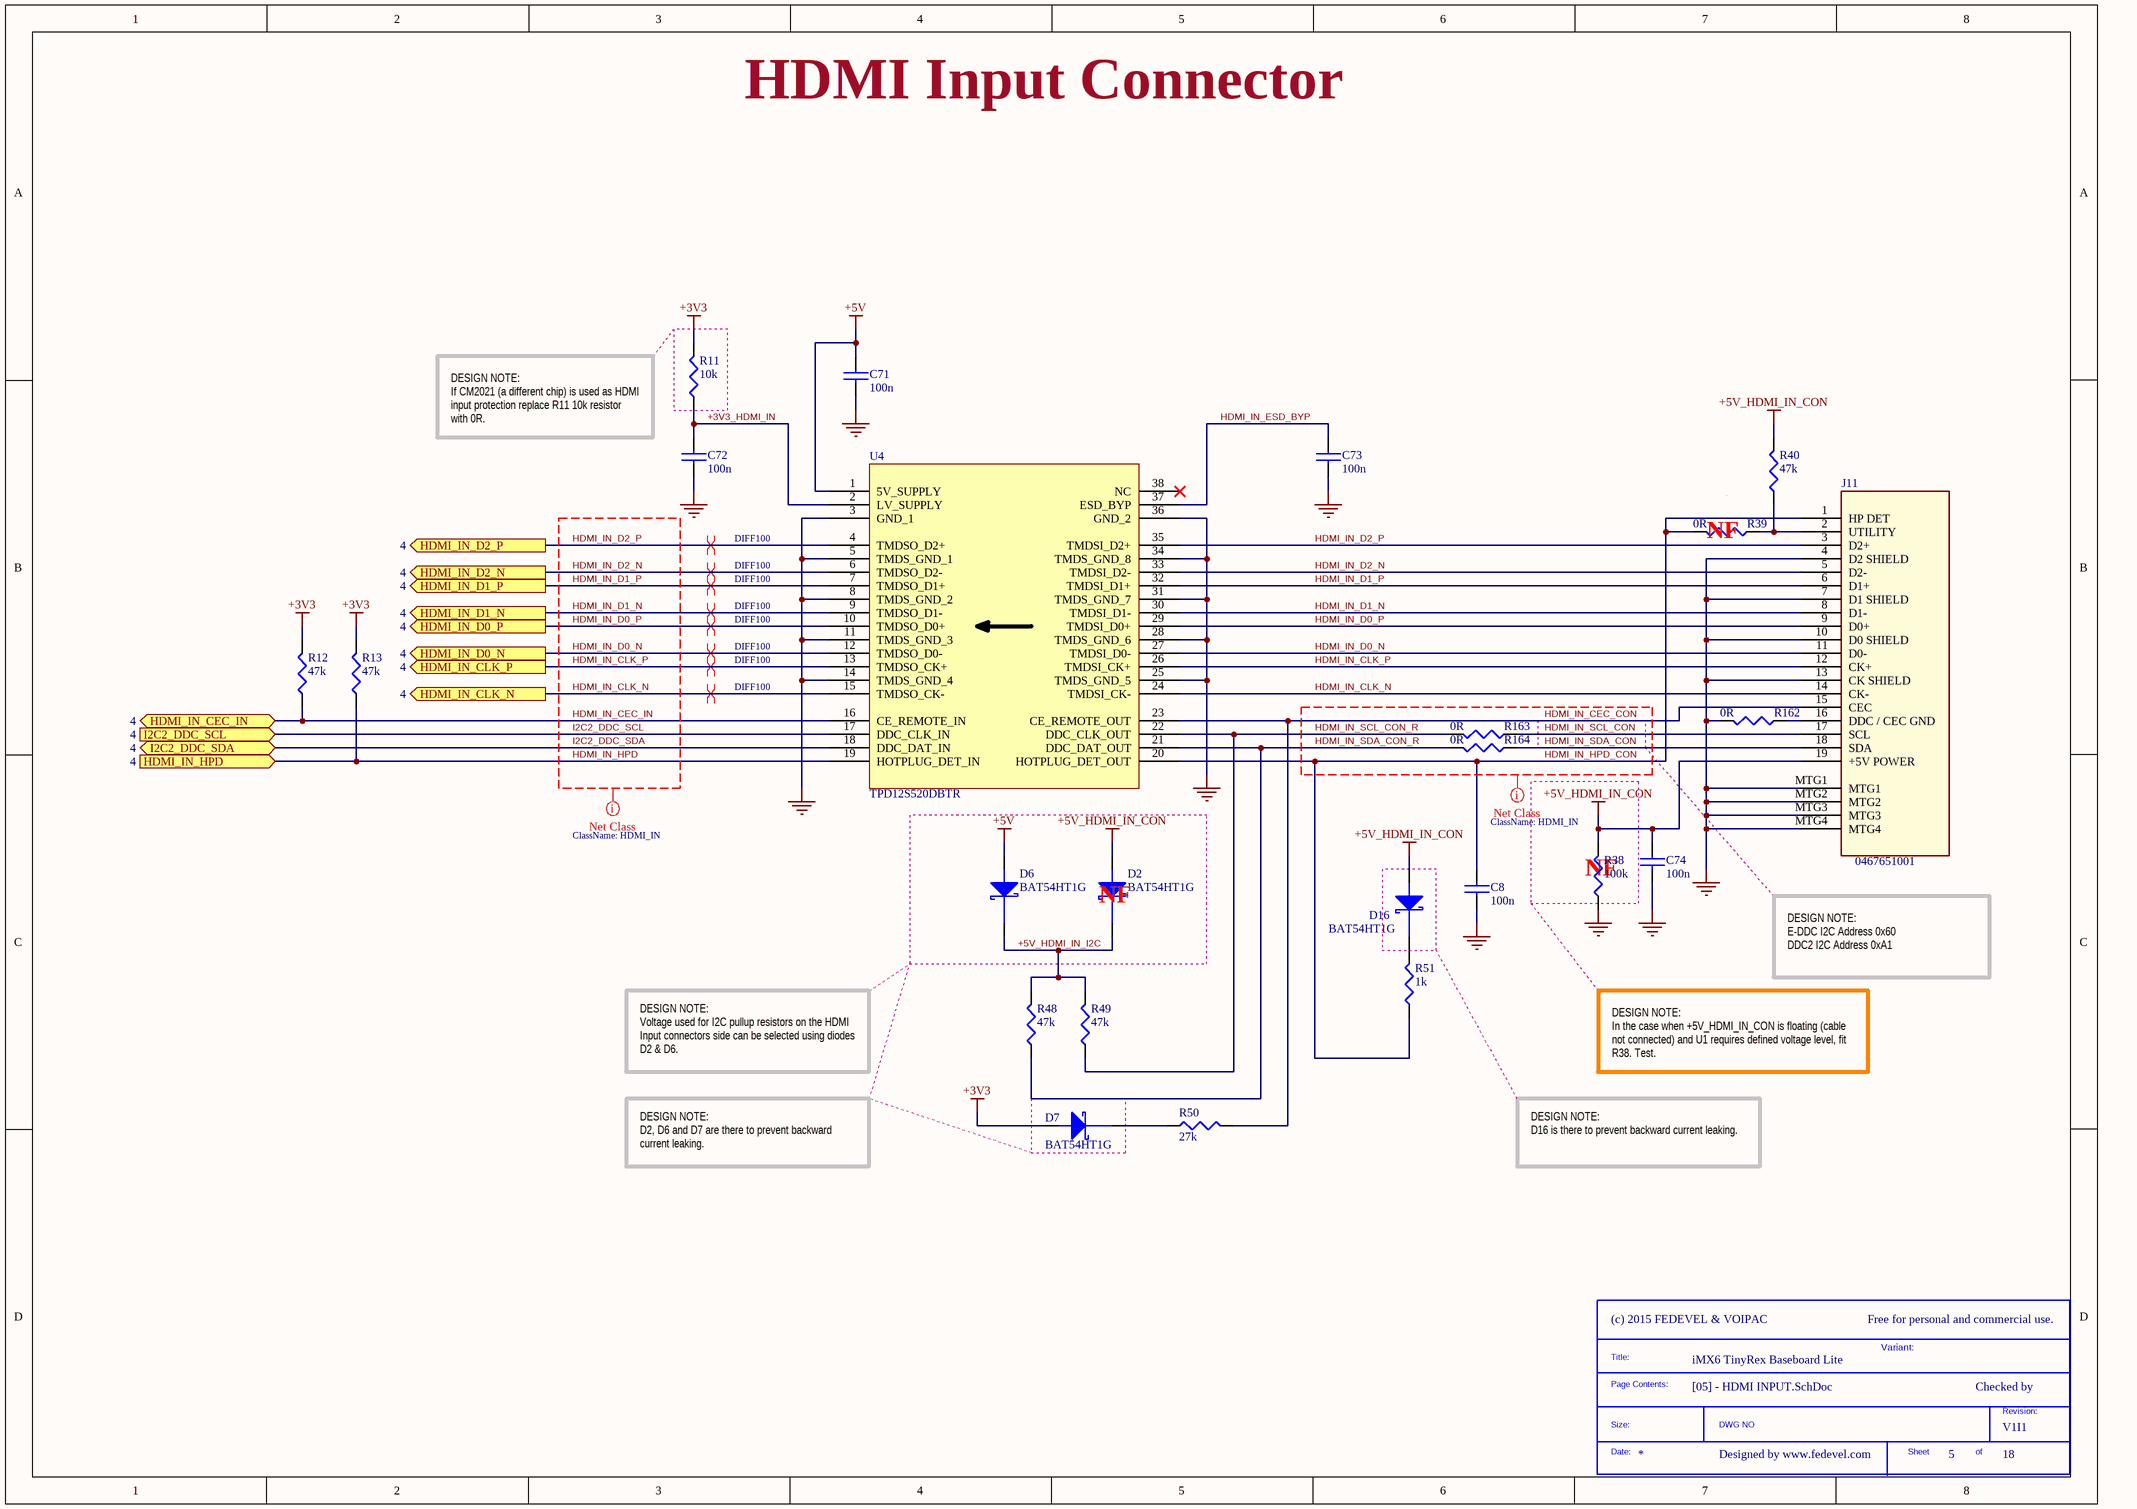
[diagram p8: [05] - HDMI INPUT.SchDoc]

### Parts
(Parts that share a designator on the sheet are numbered #1, #2 ... from top to bottom, then left to right.)
*#6  SDTitleBlock  (value not drawn)  (graphical)
C8  100n  [C0402]
C71  100n  [C0402]
C72  100n  [C0402]
C73  100n  [C0402]
C74  100n  [C0402]
D2  BAT54HT1G  [SOD323]
D6  BAT54HT1G  [SOD323]
D7  BAT54HT1G  [SOD323]
D16  BAT54HT1G  [SOD323]
J11  0467651001  [Micro_HDMI]
R11  10k  [R0402]
R12  47k  [R0402]
R13  47k  [R0402]
R38  100k  [R0402]
R39  0R  [R0402]
R40  47k  [R0402]
R48  47k  [R0402]
R49  47k  [R0402]
R50  27k  [R0402]
R51  1k  [R0402]
R162  0R  [R0402]
R163  0R  [R0402]
R164  0R  [R0402]
U4  TPD12S520DBTR  [TSSOP_38]

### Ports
HDMI_IN_CEC_IN (bidir, see 4), HDMI_IN_CLK_N (out, see 4), HDMI_IN_CLK_P (out, see 4), HDMI_IN_D0_N (out, see 4), HDMI_IN_D0_P (out, see 4), HDMI_IN_D1_N (out, see 4), HDMI_IN_D1_P (out, see 4), HDMI_IN_D2_N (out, see 4), HDMI_IN_D2_P (out, see 4), HDMI_IN_HPD (in, see 4), I2C2_DDC_SCL (in, see 4), I2C2_DDC_SDA (bidir, see 4)

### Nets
+3V3: D7.2(Anode) R11.2 R12.2 R13.2
+5V: C71.1 D6.2(Anode) U4.1(5V_SUPPLY)
+5V_HDMI_IN_CON: C74.1 D2.2(Anode) D16.2(Anode) J11.19(+5V_POWER) R38.2 R40.2
GND: C8.2 C71.2 C72.2 C73.2 C74.2 J11.4(D2_SHIELD) J11.7(D1_SHIELD) J11.10(D0_SHIELD) J11.13(CK_SHIELD) J11.MTG1 J11.MTG2 J11.MTG3 J11.MTG4 R38.1 R162.2 U4.3(GND_1) U4.5(TMDS_GND_1) U4.8(TMDS_GND_2) U4.11(TMDS_GND_3) U4.14(TMDS_GND_4) U4.25(TMDS_GND_5) U4.28(TMDS_GND_6) U4.31(TMDS_GND_7) U4.34(TMDS_GND_8) U4.36(GND_2)
+3V3_HDMI_IN: C72.1 R11.1 U4.2(LV_SUPPLY)
+5V_HDMI_IN_I2C: D2.1(Cathode) D6.1(Cathode) R48.2 R49.2
HDMI_IN_CEC_CON: J11.15(CEC) R50.2 U4.23(CE_REMOTE_OUT)
HDMI_IN_CEC_IN: R12.1 U4.16(CE_REMOTE_IN) ; port HDMI_IN_CEC_IN
HDMI_IN_CLK_N: J11.14(CK-) U4.15(TMDSO_CK-) U4.24(TMDSI_CK-) ; port HDMI_IN_CLK_N
HDMI_IN_CLK_P: J11.12(CK+) U4.13(TMDSO_CK+) U4.26(TMDSI_CK+) ; port HDMI_IN_CLK_P
HDMI_IN_D0_N: J11.11(D0-) U4.12(TMDSO_D0-) U4.27(TMDSI_D0-) ; port HDMI_IN_D0_N
HDMI_IN_D0_P: J11.9(D0+) U4.10(TMDSO_D0+) U4.29(TMDSI_D0+) ; port HDMI_IN_D0_P
HDMI_IN_D1_N: J11.8(D1-) U4.9(TMDSO_D1-) U4.30(TMDSI_D1-) ; port HDMI_IN_D1_N
HDMI_IN_D1_P: J11.6(D1+) U4.7(TMDSO_D1+) U4.32(TMDSI_D1+) ; port HDMI_IN_D1_P
HDMI_IN_D2_N: J11.5(D2-) U4.6(TMDSO_D2-) U4.33(TMDSI_D2-) ; port HDMI_IN_D2_N
HDMI_IN_D2_P: J11.3(D2+) U4.4(TMDSO_D2+) U4.35(TMDSI_D2+) ; port HDMI_IN_D2_P
HDMI_IN_ESD_BYP: C73.1 U4.37(ESD_BYP)
HDMI_IN_HPD: R13.1 U4.19(HOTPLUG_DET_IN) ; port HDMI_IN_HPD
HDMI_IN_HPD_CON: C8.1 J11.1(HP_DET) R39.2 R51.1 U4.20(HOTPLUG_DET_OUT)
HDMI_IN_SCL_CON: J11.17(SCL) R163.1
HDMI_IN_SCL_CON_R: R49.1 R163.2 U4.22(DDC_CLK_OUT)
HDMI_IN_SDA_CON: J11.18(SDA) R164.1
HDMI_IN_SDA_CON_R: R48.1 R164.2 U4.21(DDC_DAT_OUT)
I2C2_DDC_SCL: U4.17(DDC_CLK_IN) ; port I2C2_DDC_SCL
I2C2_DDC_SDA: U4.18(DDC_DAT_IN) ; port I2C2_DDC_SDA
NetD7_1: D7.1(Cathode) R50.1
NetD16_1: D16.1(Cathode) R51.2
NetJ11_2: J11.2(UTILITY) R39.1 R40.1
NetJ11_16: J11.16(DDC_/_CEC_GND) R162.1

Not connected (* = marked no-connect by the designer): U4 38(NC)*

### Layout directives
net class HDMI_IN: HDMI_IN_CEC_CON, HDMI_IN_CEC_IN, HDMI_IN_CLK_N, HDMI_IN_CLK_P, HDMI_IN_D0_N, HDMI_IN_D0_P, HDMI_IN_D1_N, HDMI_IN_D1_P, HDMI_IN_D2_N, HDMI_IN_D2_P, HDMI_IN_HPD, HDMI_IN_HPD_CON, HDMI_IN_SCL_CON, HDMI_IN_SCL_CON_R, HDMI_IN_SDA_CON, HDMI_IN_SDA_CON_R, I2C2_DDC_SCL, I2C2_DDC_SDA
differential pair; net class DIFF100: HDMI_IN_CLK_N, HDMI_IN_CLK_P, HDMI_IN_D0_N, HDMI_IN_D0_P, HDMI_IN_D1_N, HDMI_IN_D1_P, HDMI_IN_D2_N, HDMI_IN_D2_P

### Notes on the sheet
- HDMI Input Connector
- DESIGN NOTE:
  If CM2021 (a different chip) is used as HDMI input protection replace R11 10k resistor with 0R.
- DESIGN NOTE:
  E-DDC I2C Address 0x60
  DDC2 I2C Address 0xA1
- DESIGN NOTE:
  In the case when +5V_HDMI_IN_CON is floating (cable not connected) and U1 requires defined voltage level, fit R38. Test.
- DESIGN NOTE:
  Voltage used for I2C pullup resistors on the HDMI Input connectors side can be selected using diodes D2 & D6.
- DESIGN NOTE:
  D2, D6 and D7 are there to prevent backward current leaking.
- DESIGN NOTE:
  D16 is there to prevent backward current leaking.
- Free for personal and commercial use.
- Variant:
- Checked by
- Designed by www.fedevel.com

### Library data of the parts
C8 C71-C74 = C1005X5R1H104K: as C79 on sheet [15] - PWR IN, LEDS, BUTTONS, MECH
D2 D6 D7 D16 = BAT54HT1G: DIODE SCHOTTKY 30V 0.2A SOD323; Manufacturer: Fairchild Semiconductor; Current - Average Rectified (Io): 200mA; Voltage - Forward (Vf) (Max) @ If: 800mV @ 100mA; Speed: Small Signal =< 200mA (Io), Any Speed; Reverse Recovery Time (trr): 5ns; Current - Reverse Leakage @ Vr: 2µA @ 25V; Capacitance @ Vr, F: 10pF @ 1V, 1MHz; Thermal Resistance: 600°C/W Ja; .Creator: MM; .Checked PCB: used
J11 = 0467651001: CONN RCPT HDMI MICRO TYPE-D R/A; Manufacturer: Molex Inc; Connector Type: HDMI - Micro; Number of Contacts: 19; Gender: Receptacle; .Creator: MM; .Checked PCB: MM, paper model not checked
R11 = RC0402FR-0710KL: as R140 on sheet [15] - PWR IN, LEDS, BUTTONS, MECH
R12 R13 R40 R48 R49 = RC0402FR-0747KL: RES 47.0K OHM 1/16W 1% 0402 SMD; Manufacturer: Yageo; Power (Watts): 0.063W, 1/16W; .Checked PCB: used; Temperature Coefficient: ±100ppm/°C
R38 = RMCF0402FT100K: RES 100K OHM 1/16W 1% 0402 SMD; Manufacturer: Stackpole Electronics Inc; Power (Watts): 0.063W, 1/16W; .Checked PCB: used; Temperature Coefficient: ±100ppm/°C
R39 R162-R164 = RC0402JR-070RL: as R5 on sheet [04] - VIDEO INPUT
R50 = RC0402FR-0727KL: RES 27.0K OHM 1/16W 1% 0402 SMD; Manufacturer: Yageo; Power (Watts): 0.063W, 1/16W; .Checked PCB: used; Temperature Coefficient: ±100ppm/°C
R51 = RC0402FR-071KL: RES 1.00K OHM 1/16W 1% 0402 SMD; Manufacturer: Yageo; Power (Watts): 0.063W, 1/16W; .Checked PCB: used; Temperature Coefficient: ±100ppm/°C
U4 = TPD12S520DBTR: IC HDMI RCVR PORT PROT 38-TSSOP; Manufacturer: Texas Instruments; Voltage - Supply: 5V; .Creator: MM

## Sheet [06] - HDMI OUTPUT.SchDoc
size A3; DocumentNumber: 6; SheetNumber: 6; SheetTotal: 18
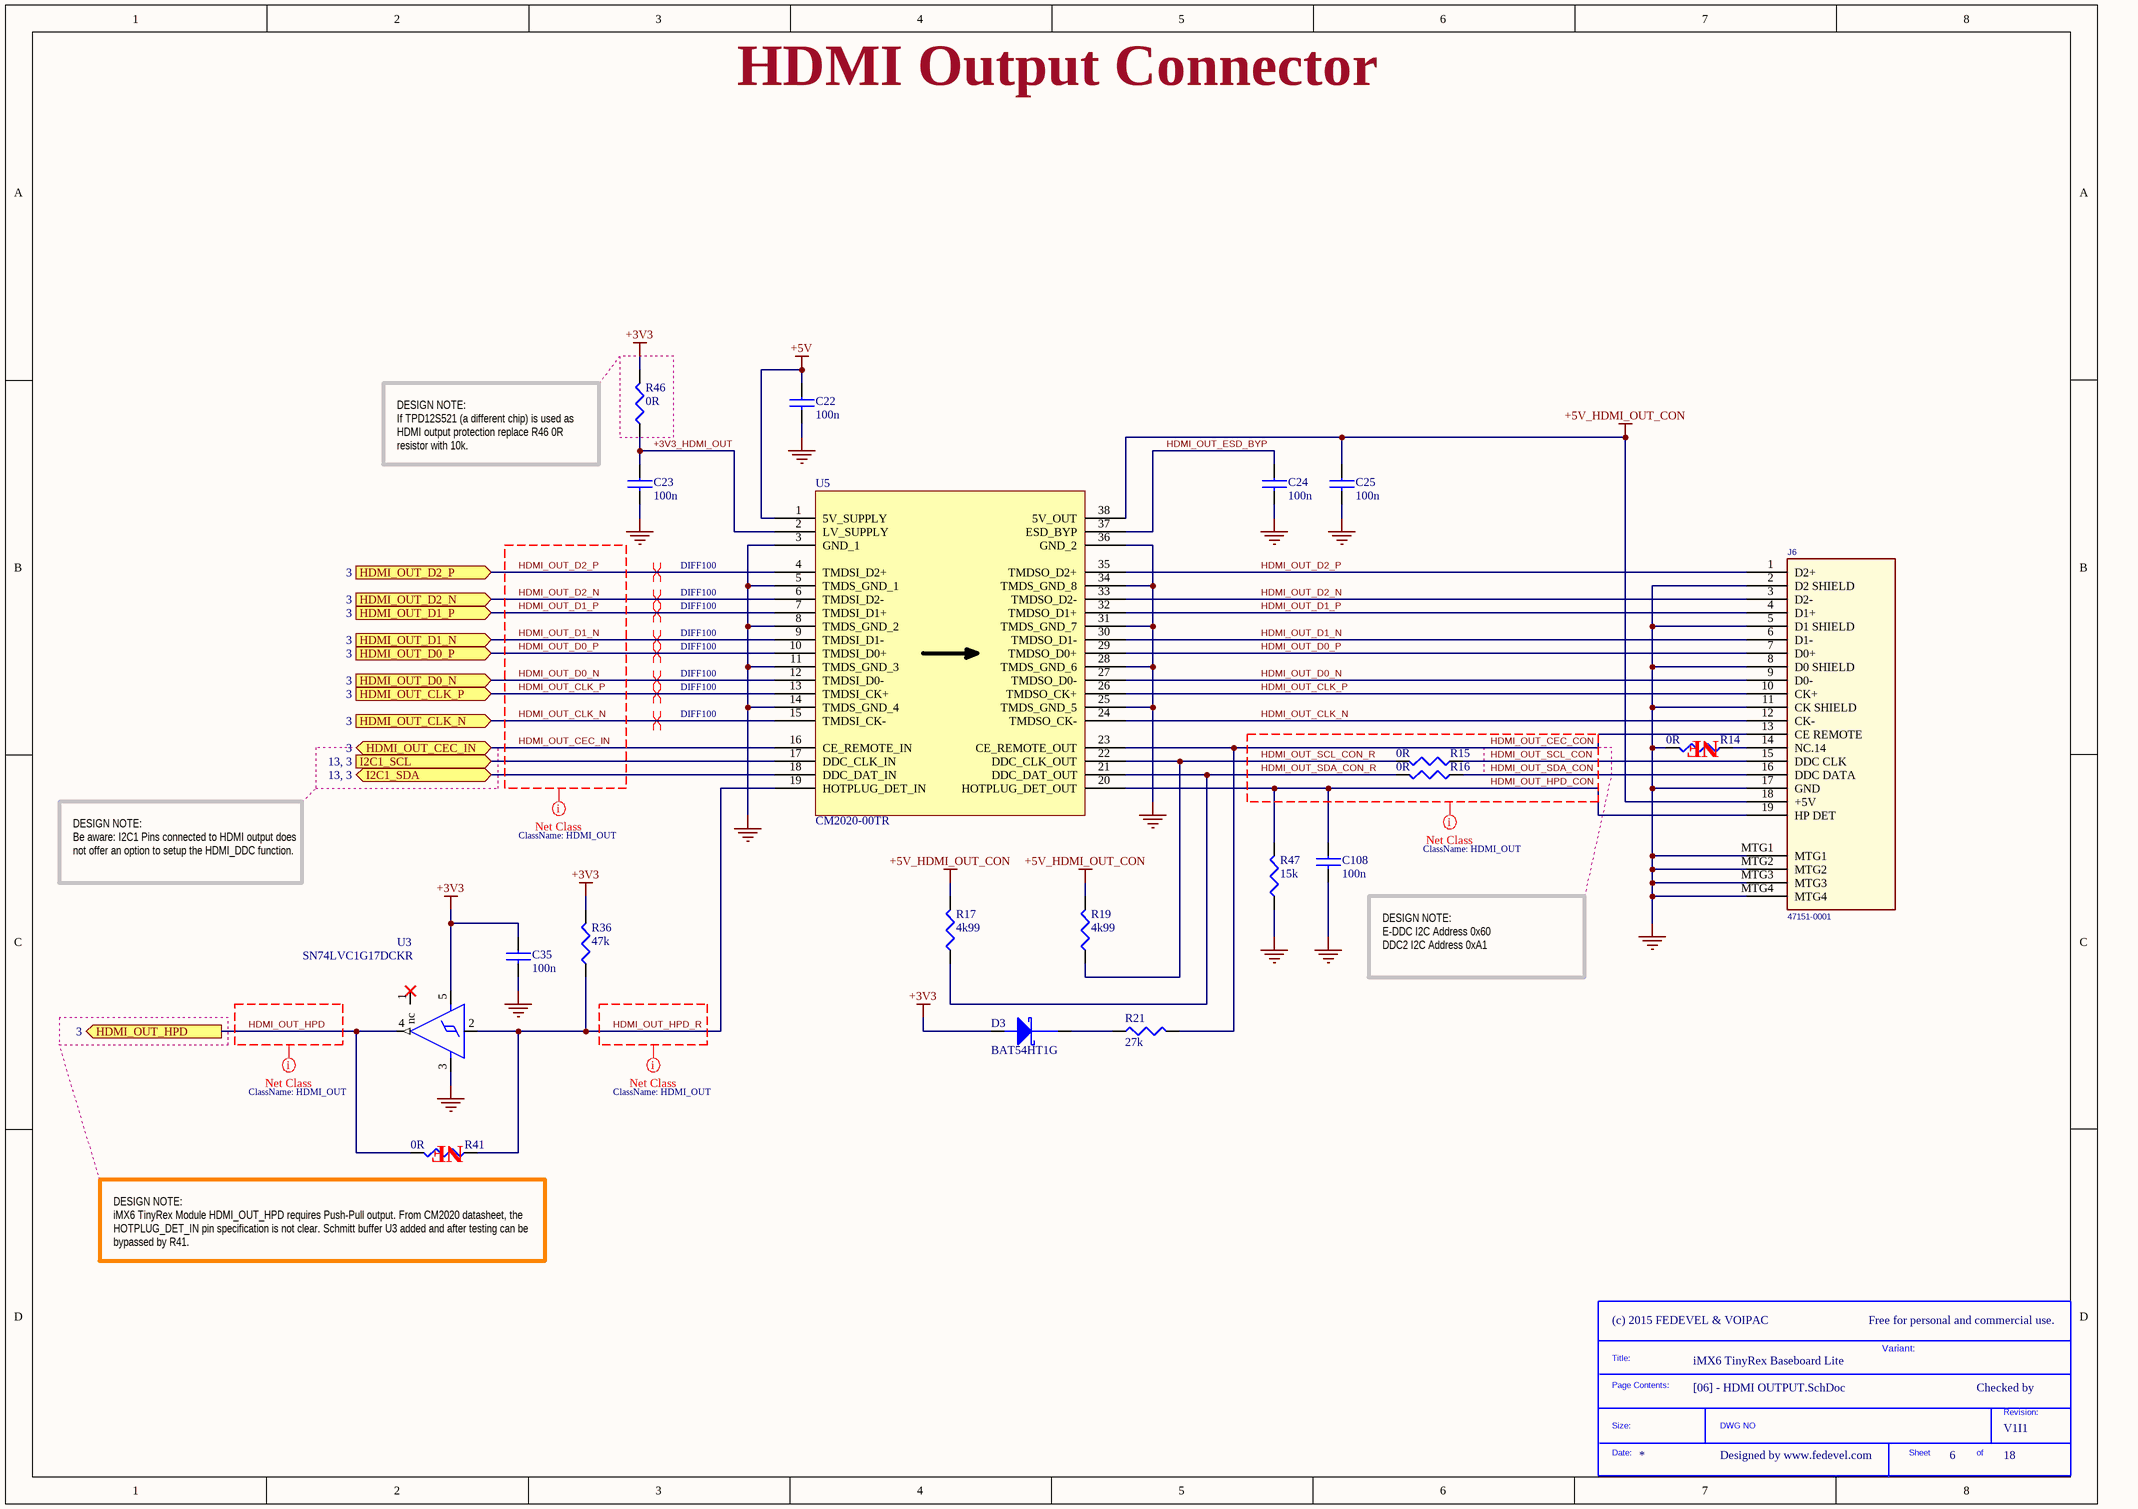
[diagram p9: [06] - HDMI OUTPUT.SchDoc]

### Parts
(Parts that share a designator on the sheet are numbered #1, #2 ... from top to bottom, then left to right.)
*#7  SDTitleBlock  (value not drawn)  (graphical)
C22  100n  [C0402]
C23  100n  [C0402]
C24  100n  [C0402]
C25  100n  [C0402]
C35  100n  [C0402]
C108  100n  [C0402]
D3  BAT54HT1G  [SOD323]
J6  47151-0001  [HDMI V1.1]
R14  0R  [R0402]
R15  0R  [R0402]
R16  0R  [R0402]
R17  4k99  [R0402]
R19  4k99  [R0402]
R21  27k  [R0402]
R36  47k  [R0402]
R41  0R  [R0402]
R46  0R  [R0402]
R47  15k  [R0402]
U3  SN74LVC1G17DCKR  [SC70_5]
U5  CM2020-00TR  [TSSOP_38]

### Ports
HDMI_OUT_CEC_IN (bidir, see 3), HDMI_OUT_CLK_N (in, see 3), HDMI_OUT_CLK_P (in, see 3), HDMI_OUT_D0_N (in, see 3), HDMI_OUT_D0_P (in, see 3), HDMI_OUT_D1_N (in, see 3), HDMI_OUT_D1_P (in, see 3), HDMI_OUT_D2_N (in, see 3), HDMI_OUT_D2_P (in, see 3), HDMI_OUT_HPD (out, see 3), I2C1_SCL (see 13, 3), I2C1_SDA (bidir, see 13, 3)

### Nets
+3V3: C35.1 D3.2(Anode) R36.2 R46.2 U3.5(NC1)
+5V: C22.1 U5.1(5V_SUPPLY)
+5V_HDMI_OUT_CON: C25.1 J6.18(+5V) R17.2 R19.2 U5.38(5V_OUT)
GND: C22.2 C23.2 C24.2 C25.2 C35.2 C108.2 J6.2(D2_SHIELD) J6.5(D1_SHIELD) J6.8(D0_SHIELD) J6.11(CK_SHIELD) J6.17(GND) J6.MTG1 J6.MTG2 J6.MTG3 J6.MTG4 R14.2 R47.1 U3.3(GND) U5.3(GND_1) U5.5(TMDS_GND_1) U5.8(TMDS_GND_2) U5.11(TMDS_GND_3) U5.14(TMDS_GND_4) U5.25(TMDS_GND_5) U5.28(TMDS_GND_6) U5.31(TMDS_GND_7) U5.34(TMDS_GND_8) U5.36(GND_2)
+3V3_HDMI_OUT: C23.1 R46.1 U5.2(LV_SUPPLY)
HDMI_OUT_CEC_CON: J6.13(CE_REMOTE) R21.2 U5.23(CE_REMOTE_OUT)
HDMI_OUT_CEC_IN: U5.16(CE_REMOTE_IN) ; port HDMI_OUT_CEC_IN
HDMI_OUT_CLK_N: J6.12(CK-) U5.15(TMDSI_CK-) U5.24(TMDSO_CK-) ; port HDMI_OUT_CLK_N
HDMI_OUT_CLK_P: J6.10(CK+) U5.13(TMDSI_CK+) U5.26(TMDSO_CK+) ; port HDMI_OUT_CLK_P
HDMI_OUT_D0_N: J6.9(D0-) U5.12(TMDSI_D0-) U5.27(TMDSO_D0-) ; port HDMI_OUT_D0_N
HDMI_OUT_D0_P: J6.7(D0+) U5.10(TMDSI_D0+) U5.29(TMDSO_D0+) ; port HDMI_OUT_D0_P
HDMI_OUT_D1_N: J6.6(D1-) U5.9(TMDSI_D1-) U5.30(TMDSO_D1-) ; port HDMI_OUT_D1_N
HDMI_OUT_D1_P: J6.4(D1+) U5.7(TMDSI_D1+) U5.32(TMDSO_D1+) ; port HDMI_OUT_D1_P
HDMI_OUT_D2_N: J6.3(D2-) U5.6(TMDSI_D2-) U5.33(TMDSO_D2-) ; port HDMI_OUT_D2_N
HDMI_OUT_D2_P: J6.1(D2+) U5.4(TMDSI_D2+) U5.35(TMDSO_D2+) ; port HDMI_OUT_D2_P
HDMI_OUT_ESD_BYP: C24.1 U5.37(ESD_BYP)
HDMI_OUT_HPD: R41.2 U3.4(O) ; port HDMI_OUT_HPD
HDMI_OUT_HPD_CON: C108.1 J6.19(HP_DET) R47.2 U5.20(HOTPLUG_DET_OUT)
HDMI_OUT_HPD_R: R36.1 R41.1 U3.2(I) U5.19(HOTPLUG_DET_IN)
HDMI_OUT_SCL_CON: J6.15(DDC_CLK) R15.1
HDMI_OUT_SCL_CON_R: R15.2 R19.1 U5.22(DDC_CLK_OUT)
HDMI_OUT_SDA_CON: J6.16(DDC_DATA) R16.1
HDMI_OUT_SDA_CON_R: R16.2 R17.1 U5.21(DDC_DAT_OUT)
I2C1_SCL: U5.17(DDC_CLK_IN) ; port I2C1_SCL
I2C1_SDA: U5.18(DDC_DAT_IN) ; port I2C1_SDA
NetD3_1: D3.1(Cathode) R21.1
NetJ6_14: J6.14(NC.14) R14.1

Not connected (* = marked no-connect by the designer): U3 1(nc)*

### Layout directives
differential pair; net class DIFF100: HDMI_OUT_CLK_N, HDMI_OUT_CLK_P, HDMI_OUT_D0_N, HDMI_OUT_D0_P, HDMI_OUT_D1_N, HDMI_OUT_D1_P, HDMI_OUT_D2_N, HDMI_OUT_D2_P
net class HDMI_OUT: HDMI_OUT_CEC_CON, HDMI_OUT_CEC_IN, HDMI_OUT_CLK_N, HDMI_OUT_CLK_P, HDMI_OUT_D0_N, HDMI_OUT_D0_P, HDMI_OUT_D1_N, HDMI_OUT_D1_P, HDMI_OUT_D2_N, HDMI_OUT_D2_P, HDMI_OUT_HPD, HDMI_OUT_HPD_CON, HDMI_OUT_HPD_R, HDMI_OUT_SCL_CON, HDMI_OUT_SCL_CON_R, HDMI_OUT_SDA_CON, HDMI_OUT_SDA_CON_R

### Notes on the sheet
- HDMI Output Connector
- DESIGN NOTE:
  If TPD12S521 (a different chip) is used as HDMI output protection replace R46 0R resistor with 10k.
- DESIGN NOTE:
  Be aware: I2C1 Pins connected to HDMI output does not offer an option to setup the HDMI_DDC function.
- DESIGN NOTE:
  E-DDC I2C Address 0x60
  DDC2 I2C Address 0xA1
- (near R41) DESIGN NOTE:
  iMX6 TinyRex Module HDMI_OUT_HPD requires Push-Pull output. From CM2020 datasheet, the HOTPLUG_DET_IN pin specification is not clear. Schmitt buffer U3 added and after testing can be bypassed by R41.
- Free for personal and commercial use.
- Variant:
- Checked by
- Designed by www.fedevel.com

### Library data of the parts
C22-C25 C35 C108 = C1005X5R1H104K: as C79 on sheet [15] - PWR IN, LEDS, BUTTONS, MECH
D3 = BAT54HT1G: as D2 on sheet [05] - HDMI INPUT
J6 = 47151-0001_v1.1: CONN RCPT 19POS HDMI RT ANG SMD; Manufacturer: Molex Connector Corporation; .Checked PCB: MM; Number of Positions: 19; Pitch: 0.50mm (.020"); Gender: Receptacle; .Version: V1.1 - Changed holes to slots
R14-R16 R41 R46 = RC0402JR-070RL: as R5 on sheet [04] - VIDEO INPUT
R17 R19 = RMCF0402FT4K99: as R6 on sheet [04] - VIDEO INPUT
R21 = RC0402FR-0727KL: as R50 on sheet [05] - HDMI INPUT
R36 = RC0402FR-0747KL: as R12 on sheet [05] - HDMI INPUT
R47 = RC0402FR-0715KL: RES 15.0K OHM 1/16W 1% 0402 SMD; Manufacturer: Yageo; Power (Watts): 0.063W, 1/16W; .Checked PCB: used; Temperature Coefficient: ±100ppm/°C
U3 = SN74LVC1G17DCKR: IC BUFFER SCHMIT TRIG SC705; Manufacturer: Texas Instruments; Logic Type: Schmitt Trigger - Buffer, Driver; Number of Elements: 1; Current - Output High, Low: 32mA, 32mA; Voltage - Supply: 1.65 V ~ 5.5 V; .Checked PCB: RF
U5 = CM2020-00TR: IC HDMI TX PORT P/I 38-TSSOP; Manufacturer: ON Semiconductor; .Creator: MM; .Checked PCB: used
